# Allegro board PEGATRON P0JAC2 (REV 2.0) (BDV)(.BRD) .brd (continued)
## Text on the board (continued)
BOTTOM: list("[Spacing] BOTTOM" "17.Line to Route Keepout" "0 MIL [DEFAULT]" "0 MIL" "0.00 MIL" "DRC ERROR CLASS/BOTTOM" "[Shape] Route Keepout/All ((-570.0 2225.0) (410.0 2765.0))" "[Line] +V3P3S_VIB ((-596.0 2584.2) (-558.0 2622.2))" list(-575.530000 2604.670000) nil)@@@list("bobo_dong" "2014/01/13 20:58:57" nil "S0DCOA89102" "g1t-p0jac.11")@@@nil | list("[Spacing] BOTTOM" "18.Line to Route Keepout" "0 MIL [DEFAULT]" "0 MIL" "0.00 MIL" "DRC ERROR CLASS/BOTTOM" "[Shape] Route Keepout/All ((-570.0 2225.0) (410.0 2765.0))" "[Line] +V3P3S_VIB ((-574.0 2606.2) (-529.72 2618.2))" list(-556.940000 2612.200000) nil)@@@list("bobo_dong" "2014/01/13 20:58:59" nil "S0DCOA89102" "g1t-p0jac.11")@@@nil | list("[Spacing] BOTTOM" "16.Microvia to Route Keepout" "0 MIL [DEFAULT]" "0 MIL" "0.00 MIL" "DRC ERROR CLASS/BOTTOM" "[Shape] Route Keepout/All ((-570.0 2225.0) (410.0 2765.0))" "[B/BVia] AU_HP_L (VIA10D4A24-L7-BOT) (-535.72 2513.77)" list(-532.440000 2510.000000) nil)@@@list("bobo_dong" "2014/01/13 20:58:57" nil "S0DCOA89102" "g1t-p0jac.11")@@@nil | list("[Spacing] BOTTOM" "8.Microvia to Route Keepout" "0 MIL [DEFAULT]" "OVERLAP" "" "DRC ERROR CLASS/BOTTOM" "[Shape] Route Keepout/All ((-570.0 2225.0) (410.0 2765.0))" "[B/BVia] AGND_AUD (VIA10D4A24-L7-BOT) (-535.72 2592.51)" list(-531.380000 2595.000000) nil)@@@list("bobo_dong" "2014/01/13 20:58:46" nil "S0DCOA89102" "g1t-p0jac.11")@@@nil | list("[Spacing] BOTTOM" "1.Line to Route Keepout" "0 MIL [DEFAULT]" "0 MIL" "0.00 MIL" "DRC ERROR CLASS/BOTTOM" "[Shape] Route Keepout/Bottom ((-570.0 2225.0) (175.0 2751.43))" "[Line] AGND_AUD ((-541.72 2606.2) (-489.2 2618.2))" list(-530.500000 2612.200000) nil)@@@list("bobo_dong" "2014/02/26 15:13:36" nil "S0DCOA89102" "g1t-p0jac.11")@@@list("vincent_kuo" "2014/02/26 15:23:34" nil "VINCENT_KUO-PC" "g1t-p0jac_byt-t.14") | list("[Spacing] BOTTOM" "2.Line to Route Keepout" "0 MIL [DEFAULT]" "0 MIL" "0.00 MIL" "DRC ERROR CLASS/BOTTOM" "[Shape] Route Keepout/Bottom ((-570.0 2225.0) (200.0 2751.43))" "[Line] AGND_AUD ((-541.72 2606.2) (-489.2 2618.2))" list(-530.500000 2612.200000) nil)@@@list("bobo_dong" "2014/02/27 14:44:05" nil "S0DCOA89102" "g1t-p0jac.11")@@@list("vincent_kuo" "2014/02/27 14:51:22" nil "VINCENT_KUO-PC" "g1t-p0jac_byt-t.14") | list("[Spacing] BOTTOM" "27.Line to Route Keepout" "0 MIL [DEFAULT]" "0 MIL" "0.00 MIL" "DRC ERROR CLASS/BOTTOM" "[Shape] Route Keepout/All ((-570.0 2225.0) (410.0 2765.0))" "[Line] GND ((-541.72 2488.09) (-513.09 2500.09))" list(-527.400000 2494.090000) nil)@@@list("bobo_dong" "2014/01/13 20:59:13" nil "S0DCOA89102" "g1t-p0jac.11")@@@nil | list("[Spacing] BOTTOM" "28.Line to Route Keepout" "0 MIL [DEFAULT]" "0 MIL" "0.00 MIL" "DRC ERROR CLASS/BOTTOM" "[Shape] Route Keepout/All ((-570.0 2225.0) (410.0 2765.0))" "[Line] GND ((-525.09 2473.0) (-498.0 2500.09))" list(-515.000000 2490.000000) nil)@@@list("bobo_dong" "2014/01/13 20:59:14" nil "S0DCOA89102" "g1t-p0jac.11")@@@nil | list("[Spacing] BOTTOM" "2.Line to Route Keepout" "0 MIL [DEFAULT]" "0 MIL" "0.00 MIL" "DRC ERROR CLASS/BOTTOM" "[Shape] Route Keepout/Bottom ((-570.0 2225.0) (175.0 2751.43))" "[Line] AGND_AUD ((-501.2 2586.0) (-469.0 2618.2))" list(-482.560000 2599.560000) nil)@@@list("bobo_dong" "2014/02/26 15:13:34" nil "S0DCOA89102" "g1t-p0jac.11")@@@list("vincent_kuo" "2014/02/26 15:23:34" nil "VINCENT_KUO-PC" "g1t-p0jac_byt-t.14") | list("[Spacing] BOTTOM" "3.Line to Route Keepout" "0 MIL [DEFAULT]" "0 MIL" "0.00 MIL" "DRC ERROR CLASS/BOTTOM" "[Shape] Route Keepout/Bottom ((-570.0 2225.0) (200.0 2751.43))" "[Line] AGND_AUD ((-501.2 2586.0) (-469.0 2618.2))" list(-482.560000 2599.560000) nil)@@@list("bobo_dong" "2014/02/27 14:44:01" nil "S0DCOA89102" "g1t-p0jac.11")@@@list("vincent_kuo" "2014/02/27 14:51:23" nil "VINCENT_KUO-PC" "g1t-p0jac_byt-t.14") | list("[Spacing] BOTTOM" "82.Shape to Route Keepout" "0 MIL [DEFAULT]" "0 MIL" "0.00 MIL" "DRC ERROR CLASS/BOTTOM" "[Shape] Route Keepout/Bottom ((-271.91 4409.28) (9.9 4687.15))" "[Bottom Shape] GND ((-679.11 -19.37) (3281.09 4854.01))" list(-261.910000 4409.280000) nil)@@@list("bobo_dong" "2014/01/13 20:49:14" nil "S0DCOA89102" "g1t-p0jac.11")@@@nil | list("[Spacing] BOTTOM" "1.Shape to Route Keepin" "0 MIL [DEFAULT]" "0 MIL" "0.00 MIL" "DRC ERROR CLASS/BOTTOM" "[Shape] Route Keepin/All ((-679.11 -19.37) (3281.09 4854.01))" "[Bottom Shape] GND ((-679.11 -19.37) (3281.09 4854.01))" list(-241.750000 4716.530000) nil)@@@list("vincent_kuo" "2014/01/15 11:51:28" nil "VINCENT_KUO-PC" "g1t-p0jac_byt-t.12")@@@list("jennifer_hsu" "2014/01/15 11:31:33" nil "JENNIFER_H-PC" "g1t-p0jac_byt-t.12") | list("[Spacing] BOTTOM" "73.Shape to Route Keepin" "0 MIL [DEFAULT]" "0 MIL" "0.00 MIL" "DRC ERROR CLASS/BOTTOM" "[Shape] Route Keepin/All ((-679.11 -19.37) (3281.09 4854.01))" "[Bottom Shape] GND ((-261.91 4419.28) (-0.1 4677.15))" list(-226.620000 4676.940000) nil)@@@list("bobo_dong" "2014/01/13 20:48:37" nil "S0DCOA89102" "g1t-p0jac.11")@@@nil | list("[Spacing] BOTTOM" "8.Shape to Route Keepin" "0 MIL [DEFAULT]" "0 MIL" "0.00 MIL" "DRC ERROR CLASS/BOTTOM" "[Shape] Route Keepin/All ((-679.03 -19.38) (3281.17 4854.0))" "[Bottom Shape] GND ((-679.11 -19.37) (3281.09 4854.01))" list(-19.380000 -0.010000) nil)@@@list("bobo_dong" "2014/02/26 15:13:26" nil "S0DCOA89102" "g1t-p0jac.11")@@@list("vincent_kuo" "2014/02/26 12:03:50" nil "VINCENT_KUO-PC" "g1t-p0jac_byt-t.14") | list("[Spacing] BOTTOM" "78.Shape to Route Keepout" "0 MIL [DEFAULT]" "0 MIL" "0.00 MIL" "DRC ERROR CLASS/BOTTOM" "[Shape] Route Keepout/All ((-570.0 2225.0) (410.0 2765.0))" "[Bottom Shape] GND ((-679.11 -19.37) (3281.09 4854.01))" list(64.990000 2610.850000) nil)@@@list("bobo_dong" "2014/01/13 20:49:11" nil "S0DCOA89102" "g1t-p0jac.11")@@@nil | list("[Spacing] BOTTOM" "1.Shape to Route Keepout" "0 MIL [DEFAULT]" "0 MIL" "0.00 MIL" "DRC ERROR CLASS/BOTTOM" "[Shape] Route Keepout/Bottom ((-570.0 2225.0) (200.0 2751.43))" "[Bottom Shape] GND ((-679.11 -19.37) (3281.09 4854.01))" list(65.000000 2610.860000) nil)@@@list("bobo_dong" "2014/02/27 14:43:52" nil "S0DCOA89102" "g1t-p0jac.11")@@@list("vincent_kuo" "2014/02/27 14:51:21" nil "VINCENT_KUO-PC" "g1t-p0jac_byt-t.14") | list("[Spacing] BOTTOM" "12.Shape to Route Keepout" "0 MIL [DEFAULT]" "0 MIL" "0.00 MIL" "DRC ERROR CLASS/BOTTOM" "[Shape] Route Keepout/Bottom ((-570.0 2225.0) (175.0 2751.43))" "[Bottom Shape] GND ((-679.11 -19.37) (3281.09 4854.01))" list(65.000000 2610.860000) nil)@@@list("bobo_dong" "2014/02/25 09:09:09" nil "s0dcoa89102" "g1t-p0jac.11")@@@list("vincent_kuo" "2014/02/26 12:03:59" nil "VINCENT_KUO-PC" "g1t-p0jac_byt-t.14") | list("[Spacing] BOTTOM" "31.Line to Route Keepout" "0 MIL [DEFAULT]" "0 MIL" "0.00 MIL" "DRC ERROR CLASS/BOTTOM" "[Shape] Route Keepout/All ((-570.0 2225.0) (410.0 2765.0))" "[Line] +V1P8S ((86.6 2695.11) (96.6 2791.23))" list(91.600000 2725.460000) nil)@@@list("bobo_dong" "2014/01/13 20:59:18" nil "S0DCOA89102" "g1t-p0jac.11")@@@nil | list("[Spacing] BOTTOM" "30.Line to Route Keepout" "0 MIL [DEFAULT]" "0 MIL" "0.00 MIL" "DRC ERROR CLASS/BOTTOM" "[Shape] Route Keepout/All ((-570.0 2225.0) (410.0 2765.0))" "[Line] GND ((117.23 2762.48) (134.23 2801.98))" list(125.730000 2770.980000) nil)@@@list("bobo_dong" "2014/01/13 20:59:16" nil "S0DCOA89102" "g1t-p0jac.11")@@@nil | list("[Physical] BOTTOM" "10.Pad/Pad Direct Connect" "VIAS_PINS_ONLY [85OHM(DP_#1/#2/5/200)]" "ALL_ALLOWED" "" "DRC ERROR CLASS/BOTTOM" "[SmdPin] MCSI_2_CLK_DP_CON (<uTiL>cId875<uTiL>.3) (130.9 3857.59)" "[SmdPin] MCSI_2_CLK_DP_CON (<uTiL>cId2109<uTiL>.4) (128.93 3855.62)" list(128.930000 3855.620000) nil)@@@list("bobo_dong" "2014/01/27 15:52:09" nil "s0dcoa89102" "g1t-p0jac.11")@@@list("vincent_kuo" "2014/02/26 15:23:44" nil "VINCENT_KUO-PC" "g1t-p0jac_byt-t.14") | list("[Physical] BOTTOM" "11.Pad/Pad Direct Connect" "VIAS_PINS_ONLY [85OHM(DP_#1/#2/5/200)]" "ALL_ALLOWED" "" "DRC ERROR CLASS/BOTTOM" "[SmdPin] MCSI_2_CLK_DP (<uTiL>cId875<uTiL>.4) (130.9 3808.37)" "[SmdPin] MCSI_2_CLK_DP (<uTiL>cId2109<uTiL>.3) (128.93 3810.34)" list(128.930000 3810.340000) nil)@@@list("bobo_dong" "2014/01/27 15:52:10" nil "s0dcoa89102" "g1t-p0jac.11")@@@list("vincent_kuo" "2014/02/26 15:23:46" nil "VINCENT_KUO-PC" "g1t-p0jac_byt-t.14") | list("[Physical] BOTTOM" "9.Pad/Pad Direct Connect" "VIAS_PINS_ONLY [85OHM(DP_#1/#2/5/200)]" "ALL_ALLOWED" "" "DRC ERROR CLASS/BOTTOM" "[SmdPin] MCSI_2_CLK_DN_CON (<uTiL>cId875<uTiL>.2) (152.56 3857.59)" "[SmdPin] MCSI_2_CLK_DN_CON (<uTiL>cId2109<uTiL>.2) (154.53 3855.62)" list(154.530000 3855.620000) nil)@@@list("bobo_dong" "2014/01/27 15:52:08" nil "s0dcoa89102" "g1t-p0jac.11")@@@list("vincent_kuo" "2014/02/26 15:23:43" nil "VINCENT_KUO-PC" "g1t-p0jac_byt-t.14") | list("[Physical] BOTTOM" "8.Pad/Pad Direct Connect" "VIAS_PINS_ONLY [85OHM(DP_#1/#2/5/200)]" "ALL_ALLOWED" "" "DRC ERROR CLASS/BOTTOM" "[SmdPin] MCSI_2_CLK_DN (<uTiL>cId875<uTiL>.1) (152.56 3808.37)" "[SmdPin] MCSI_2_CLK_DN (<uTiL>cId2109<uTiL>.1) (154.53 3810.34)" list(154.530000 3810.340000) nil)@@@list("bobo_dong" "2014/01/27 15:52:07" nil "s0dcoa89102" "g1t-p0jac.11")@@@list("vincent_kuo" "2014/02/26 15:23:42" nil "VINCENT_KUO-PC" "g1t-p0jac_byt-t.14") | list("[Spacing] BOTTOM" "29.Line to Route Keepout" "0 MIL [DEFAULT]" "0 MIL" "0.00 MIL" "DRC ERROR CLASS/BOTTOM" "[Shape] Route Keepout/All ((-570.0 2225.0) (410.0 2765.0))" "[Line] GND ((148.23 2762.48) (165.23 2795.77))" list(156.730000 2770.980000) nil)@@@list("bobo_dong" "2014/01/13 20:59:16" nil "S0DCOA89102" "g1t-p0jac.11")@@@nil | list("[Physical] BOTTOM" "5.Pad/Pad Direct Connect" "VIAS_PINS_ONLY [85OHM(DP_#1/#2/5/200)]" "ALL_ALLOWED" "" "DRC ERROR CLASS/BOTTOM" "[SmdPin] MCSI_2_DATA_DP_CON (<uTiL>cId876<uTiL>.3) (178.9 3857.59)" "[SmdPin] MCSI_2_DATA_DP_CON (<uTiL>cId2108<uTiL>.4) (176.93 3855.62)" list(176.930000 3855.620000) nil)@@@list("bobo_dong" "2014/01/27 15:52:04" nil "s0dcoa89102" "g1t-p0jac.11")@@@list("vincent_kuo" "2014/02/26 15:23:39" nil "VINCENT_KUO-PC" "g1t-p0jac_byt-t.14") | list("[Physical] BOTTOM" "4.Pad/Pad Direct Connect" "VIAS_PINS_ONLY [85OHM(DP_#1/#2/5/200)]" "ALL_ALLOWED" "" "DRC ERROR CLASS/BOTTOM" "[SmdPin] MCSI_2_DATA_DP (<uTiL>cId876<uTiL>.4) (178.9 3808.37)" "[SmdPin] MCSI_2_DATA_DP (<uTiL>cId2108<uTiL>.3) (176.93 3810.34)" list(176.930000 3810.340000) nil)@@@list("bobo_dong" "2014/01/27 15:52:03" nil "s0dcoa89102" "g1t-p0jac.11")@@@list("vincent_kuo" "2014/02/26 15:23:38" nil "VINCENT_KUO-PC" "g1t-p0jac_byt-t.14") | list("[Spacing] BOTTOM" "80.Shape to Route Keepout" "0 MIL [DEFAULT]" "0 MIL" "0.00 MIL" "DRC ERROR CLASS/BOTTOM" "[Shape] Route Keepout/All ((175.42 4013.55) (297.04 4057.17))" "[Bottom Shape] GND ((-679.11 -19.37) (3281.09 4854.01))" list(197.230000 4057.170000) nil)@@@list("bobo_dong" "2014/01/13 20:49:12" nil "S0DCOA89102" "g1t-p0jac.11")@@@nil | list("[Physical] BOTTOM" "6.Pad/Pad Direct Connect" "VIAS_PINS_ONLY [85OHM(DP_#1/#2/5/200)]" "ALL_ALLOWED" "" "DRC ERROR CLASS/BOTTOM" "[SmdPin] MCSI_2_DATA_DN_CON (<uTiL>cId876<uTiL>.2) (200.56 3857.59)" "[SmdPin] MCSI_2_DATA_DN_CON (<uTiL>cId2108<uTiL>.2) (202.53 3855.62)" list(202.530000 3855.620000) nil)@@@list("bobo_dong" "2014/01/27 15:52:05" nil "s0dcoa89102" "g1t-p0jac.11")@@@list("vincent_kuo" "2014/02/26 15:23:40" nil "VINCENT_KUO-PC" "g1t-p0jac_byt-t.14") | list("[Physical] BOTTOM" "7.Pad/Pad Direct Connect" "VIAS_PINS_ONLY [85OHM(DP_#1/#2/5/200)]" "ALL_ALLOWED" "" "DRC ERROR CLASS/BOTTOM" "[SmdPin] MCSI_2_DATA_DN (<uTiL>cId876<uTiL>.1) (200.56 3808.37)" "[SmdPin] MCSI_2_DATA_DN (<uTiL>cId2108<uTiL>.1) (202.53 3810.34)" list(202.530000 3810.340000) nil)@@@list("bobo_dong" "2014/01/27 15:52:06" nil "s0dcoa89102" "g1t-p0jac.11")@@@list("vincent_kuo" "2014/02/26 15:23:41" nil "VINCENT_KUO-PC" "g1t-p0jac_byt-t.14") | list("[Spacing] BOTTOM" "81.Shape to Route Keepin" "0 MIL [DEFAULT]" "0 MIL" "0.00 MIL" "DRC ERROR CLASS/BOTTOM" "[Shape] Route Keepin/All ((-679.11 -19.37) (3281.09 4854.01))" "[Bottom Shape] GND ((-679.11 -19.37) (3281.09 4854.01))" list(204.240000 4334.330000) nil)@@@list("bobo_dong" "2014/01/13 20:49:13" nil "S0DCOA89102" "g1t-p0jac.11")@@@nil | list("[Spacing] BOTTOM" "26.Line to Route Keepout" "0 MIL [DEFAULT]" "0 MIL" "0.00 MIL" "DRC ERROR CLASS/BOTTOM" "[Shape] Route Keepout/All ((-570.0 2225.0) (410.0 2765.0))" "[Line] CPVPP ((257.91 2632.09) (277.03 2639.09))" list(273.530000 2635.590000) nil)@@@list("bobo_dong" "2014/01/13 20:59:12" nil "S0DCOA89102" "g1t-p0jac.11")@@@nil | list("[Spacing] BOTTOM" "7.Line to Route Keepout" "0 MIL [DEFAULT]" "0 MIL" "0.00 MIL" "DRC ERROR CLASS/BOTTOM" "[Shape] Route Keepout/All ((-570.0 2225.0) (410.0 2765.0))" "[Line] +V1P8S_AUD_PVDD ((253.35 2616.35) (277.03 2623.35))" list(273.530000 2619.850000) nil)@@@list("bobo_dong" "2014/01/13 20:58:45" nil "S0DCOA89102" "g1t-p0jac.11")@@@nil | list("[Spacing] BOTTOM" "24.Line to Route Keepout" "0 MIL [DEFAULT]" "0 MIL" "0.00 MIL" "DRC ERROR CLASS/BOTTOM" "[Shape] Route Keepout/All ((-570.0 2225.0) (410.0 2765.0))" "[Line] N55583183 ((249.15 2584.85) (277.03 2591.85))" list(273.530000 2588.350000) nil)@@@list("bobo_dong" "2014/01/13 20:59:07" nil "S0DCOA89102" "g1t-p0jac.11")@@@nil | list("[Spacing] BOTTOM" "19.Line to Route Keepout" "0 MIL [DEFAULT]" "0 MIL" "0.00 MIL" "DRC ERROR CLASS/BOTTOM" "[Shape] Route Keepout/All ((-570.0 2225.0) (410.0 2765.0))" "[Line] N55583175 ((250.9 2569.1) (277.03 2576.1))" list(273.530000 2572.600000) nil)@@@list("bobo_dong" "2014/01/13 20:59:00" nil "S0DCOA89102" "g1t-p0jac.11")@@@nil | list("[Spacing] BOTTOM" "20.Line to Route Keepout" "0 MIL [DEFAULT]" "0 MIL" "0.00 MIL" "DRC ERROR CLASS/BOTTOM" "[Shape] Route Keepout/All ((-570.0 2225.0) (410.0 2765.0))" "[Line] N55583031 ((251.61 2537.61) (277.03 2544.61))" list(273.530000 2541.110000) nil)@@@list("bobo_dong" "2014/01/13 20:59:00" nil "S0DCOA89102" "g1t-p0jac.11")@@@nil | list("[Spacing] BOTTOM" "11.Line to Route Keepout" "0 MIL [DEFAULT]" "0 MIL" "0.00 MIL" "DRC ERROR CLASS/BOTTOM" "[Shape] Route Keepout/All ((-570.0 2225.0) (410.0 2765.0))" "[Line] N55584679 ((251.64 2490.36) (277.03 2497.36))" list(273.530000 2493.860000) nil)@@@list("bobo_dong" "2014/01/13 20:58:50" nil "S0DCOA89102" "g1t-p0jac.11")@@@nil | list("[Spacing] BOTTOM" "9.Microvia to Route Keepout" "0 MIL [DEFAULT]" "OVERLAP" "" "DRC ERROR CLASS/BOTTOM" "[Shape] Route Keepout/All ((-570.0 2225.0) (410.0 2765.0))" "[B/BVia] AGND_AUD (VIA10D4A24-L7-BOT) (273.53 2604.1)" list(275.000000 2608.880000) nil)@@@list("bobo_dong" "2014/01/13 20:58:47" nil "S0DCOA89102" "g1t-p0jac.11")@@@nil | list("[Spacing] BOTTOM" "25.Microvia to Route Keepout" "0 MIL [DEFAULT]" "0 MIL" "0.00 MIL" "DRC ERROR CLASS/BOTTOM" "[Shape] Route Keepout/All ((-570.0 2225.0) (410.0 2765.0))" "[B/BVia] N55582751 (VIA10D4A24-L7-BOT) (273.53 2556.85)" list(275.000000 2561.630000) nil)@@@list("bobo_dong" "2014/01/13 20:59:08" nil "S0DCOA89102" "g1t-p0jac.11")@@@nil | list("[Spacing] BOTTOM" "23.Line to Route Keepout" "0 MIL [DEFAULT]" "0 MIL" "0.00 MIL" "DRC ERROR CLASS/BOTTOM" "[Shape] Route Keepout/All ((-570.0 2225.0) (410.0 2765.0))" "[Line] N60826251 ((231.59 2431.0) (303.34 2441.0))" list(294.600000 2436.000000) nil)@@@list("bobo_dong" "2014/01/13 20:59:06" nil "S0DCOA89102" "g1t-p0jac.11")@@@nil | list("[Spacing] BOTTOM" "22.Line to Route Keepout" "0 MIL [DEFAULT]" "0 MIL" "0.00 MIL" "DRC ERROR CLASS/BOTTOM" "[Shape] Route Keepout/All ((-570.0 2225.0) (410.0 2765.0))" "[Line] N60826251 ((294.84 2432.5) (302.62 2440.28))" list(299.120000 2436.780000) nil)@@@list("bobo_dong" "2014/01/13 20:59:04" nil "S0DCOA89102" "g1t-p0jac.11")@@@nil | list("[Physical] BOTTOM" "101.Pad/Pad Direct Connect" "VIAS_PINS_ONLY [(GND_DEFAULT)]" "ALL_ALLOWED" "" "DRC ERROR CLASS/BOTTOM" "[ThruPin] GND (<uTiL>cId50<uTiL>.52) (306.23 2628.48)" "[SmdPin] GND (<uTiL>cId50<uTiL>.49) (385.73 2548.98)" list(306.230000 2628.480000) nil)@@@list("bobo_dong" "2014/01/27 15:53:54" nil "s0dcoa89102" "g1t-p0jac.11")@@@list("vincent_kuo" "2014/02/26 15:25:41" nil "VINCENT_KUO-PC" "g1t-p0jac_byt-t.14") | list("[Physical] BOTTOM" "100.Pad/Pad Direct Connect" "VIAS_PINS_ONLY [(GND_DEFAULT)]" "ALL_ALLOWED" "" "DRC ERROR CLASS/BOTTOM" "[ThruPin] GND (<uTiL>cId50<uTiL>.56) (306.23 2548.98)" "[SmdPin] GND (<uTiL>cId50<uTiL>.49) (385.73 2548.98)" list(306.230000 2548.980000) nil)@@@list("bobo_dong" "2014/01/27 15:53:53" nil "s0dcoa89102" "g1t-p0jac.11")@@@list("vincent_kuo" "2014/02/26 15:25:40" nil "VINCENT_KUO-PC" "g1t-p0jac_byt-t.14") | list("[Physical] BOTTOM" "104.Pad/Pad Direct Connect" "VIAS_PINS_ONLY [(GND_DEFAULT)]" "ALL_ALLOWED" "" "DRC ERROR CLASS/BOTTOM" "[ThruPin] GND (<uTiL>cId50<uTiL>.59) (306.23 2469.48)" "[SmdPin] GND (<uTiL>cId50<uTiL>.49) (385.73 2548.98)" list(306.230000 2469.480000) nil)@@@list("bobo_dong" "2014/01/27 15:53:57" nil "s0dcoa89102" "g1t-p0jac.11")@@@list("vincent_kuo" "2014/02/26 15:25:44" nil "VINCENT_KUO-PC" "g1t-p0jac_byt-t.14") | list("[Spacing] BOTTOM" "12.Line to Route Keepout" "0 MIL [DEFAULT]" "0 MIL" "0.00 MIL" "DRC ERROR CLASS/BOTTOM" "[Shape] Route Keepout/All ((-570.0 2225.0) (410.0 2765.0))" "[Line] N60826256 ((311.36 2420.96) (318.36 2440.28))" list(314.860000 2436.780000) nil)@@@list("bobo_dong" "2014/01/13 20:58:51" nil "S0DCOA89102" "g1t-p0jac.11")@@@nil | list("[Spacing] BOTTOM" "6.Line to Route Keepout" "0 MIL [DEFAULT]" "0 MIL" "0.00 MIL" "DRC ERROR CLASS/BOTTOM" "[Shape] Route Keepout/All ((-570.0 2225.0) (410.0 2765.0))" "[Line] N60556074 ((327.11 2419.02) (334.11 2440.28))" list(330.610000 2436.780000) nil)@@@list("bobo_dong" "2014/01/13 20:58:44" nil "S0DCOA89102" "g1t-p0jac.11")@@@nil | list("[Spacing] BOTTOM" "13.Line to Route Keepout" "0 MIL [DEFAULT]" "0 MIL" "0.00 MIL" "DRC ERROR CLASS/BOTTOM" "[Shape] Route Keepout/All ((-570.0 2225.0) (410.0 2765.0))" "[Line] AU_HP_L ((337.3 2708.54) (349.86 2721.1))" list(346.360000 2712.040000) nil)@@@list("bobo_dong" "2014/01/13 20:58:54" nil "S0DCOA89102" "g1t-p0jac.11")@@@nil | list("[Spacing] BOTTOM" "14.Line to Route Keepout" "0 MIL [DEFAULT]" "0 MIL" "0.00 MIL" "DRC ERROR CLASS/BOTTOM" "[Shape] Route Keepout/All ((-570.0 2225.0) (410.0 2765.0))" "[Line] AU_HP_L ((342.86 2657.68) (349.86 2715.54))" list(346.360000 2661.640000) nil)@@@list("bobo_dong" "2014/01/13 20:58:54" nil "S0DCOA89102" "g1t-p0jac.11")@@@nil | list("[Spacing] BOTTOM" "97.Line to Route Keepout" "0 MIL [DEFAULT]" "0 MIL" "0.00 MIL" "DRC ERROR CLASS/BOTTOM" "[Shape] Route Keepout/All ((-570.0 2225.0) (410.0 2765.0))" "[Line] AGND_AUD ((342.86 2412.14) (349.86 2440.28))" list(346.360000 2436.780000) nil)@@@list("bobo_dong" "2014/01/13 20:51:46" nil "S0DCOA89102" "g1t-p0jac.11")@@@nil | list("[Spacing] BOTTOM" "15.Thru Via to Route Keepout" "0 MIL [DEFAULT]" "0 MIL" "0.00 MIL" "DRC ERROR CLASS/BOTTOM" "[Shape] Route Keepout/All ((-570.0 2225.0) (410.0 2765.0))" "[ThruVia] AU_HP_L (VIA20D10A32) (340.8 2717.6)" list(350.000000 2721.520000) nil)@@@list("bobo_dong" "2014/01/13 20:58:55" nil "S0DCOA89102" "g1t-p0jac.11")@@@nil | list("[Spacing] BOTTOM" "74.Shape to Route Keepout" "0 MIL [DEFAULT]" "0 MIL" "0.00 MIL" "DRC ERROR CLASS/BOTTOM" "[Shape] Route Keepout/All ((-570.0 2225.0) (410.0 2765.0))" "[Bottom Shape] GND ((294.0 2458.0) (477.0 2640.0))" list(351.640000 2640.000000) nil)@@@list("bobo_dong" "2014/01/13 20:49:07" nil "S0DCOA89102" "g1t-p0jac.11")@@@nil | list("[Physical] BOTTOM" "98.Pad/Pad Direct Connect" "VIAS_PINS_ONLY [(GND_DEFAULT)]" "ALL_ALLOWED" "" "DRC ERROR CLASS/BOTTOM" "[ThruPin] GND (<uTiL>cId50<uTiL>.55) (359.23 2548.98)" "[SmdPin] GND (<uTiL>cId50<uTiL>.49) (385.73 2548.98)" list(359.230000 2548.980000) nil)@@@list("bobo_dong" "2014/01/27 15:53:51" nil "s0dcoa89102" "g1t-p0jac.11")@@@list("vincent_kuo" "2014/02/26 15:25:38" nil "VINCENT_KUO-PC" "g1t-p0jac_byt-t.14") | list("[Spacing] BOTTOM" "10.Line to Route Keepout" "0 MIL [DEFAULT]" "0 MIL" "0.00 MIL" "DRC ERROR CLASS/BOTTOM" "[Shape] Route Keepout/All ((-570.0 2225.0) (410.0 2765.0))" "[Line] LRCK2 ((358.61 2657.68) (365.61 2721.61))" list(362.110000 2699.530000) nil)@@@list("bobo_dong" "2014/01/13 20:58:49" nil "S0DCOA89102" "g1t-p0jac.11")@@@nil | list("[Spacing] BOTTOM" "5.Line to Route Keepout" "0 MIL [DEFAULT]" "0 MIL" "0.00 MIL" "DRC ERROR CLASS/BOTTOM" "[Shape] Route Keepout/All ((-570.0 2225.0) (410.0 2765.0))" "[Line] IN2N ((357.11 2406.31) (367.11 2441.78))" list(362.110000 2436.780000) nil)@@@list("bobo_dong" "2014/01/13 20:58:43" nil "S0DCOA89102" "g1t-p0jac.11")@@@nil | list("[Spacing] BOTTOM" "21.Line to Route Keepout" "0 MIL [DEFAULT]" "0 MIL" "0.00 MIL" "DRC ERROR CLASS/BOTTOM" "[Shape] Route Keepout/All ((-570.0 2225.0) (410.0 2765.0))" "[Line] IN2P ((372.86 2382.86) (382.86 2441.78))" list(377.860000 2436.780000) nil)@@@list("bobo_dong" "2014/01/13 20:59:01" nil "S0DCOA89102" "g1t-p0jac.11")@@@nil | list("[Physical] BOTTOM" "99.Pad/Pad Direct Connect" "VIAS_PINS_ONLY [(GND_DEFAULT)]" "ALL_ALLOWED" "" "DRC ERROR CLASS/BOTTOM" "[ThruPin] GND (<uTiL>cId50<uTiL>.51) (385.73 2628.48)" "[SmdPin] GND (<uTiL>cId50<uTiL>.49) (385.73 2548.98)" list(385.730000 2628.480000) nil)@@@list("bobo_dong" "2014/01/27 15:53:52" nil "s0dcoa89102" "g1t-p0jac.11")@@@list("vincent_kuo" "2014/02/26 15:25:39" nil "VINCENT_KUO-PC" "g1t-p0jac_byt-t.14") | list("[Physical] BOTTOM" "103.Pad/Pad Direct Connect" "VIAS_PINS_ONLY [(GND_DEFAULT)]" "ALL_ALLOWED" "" "DRC ERROR CLASS/BOTTOM" "[ThruPin] GND (<uTiL>cId50<uTiL>.58) (385.73 2469.48)" "[SmdPin] GND (<uTiL>cId50<uTiL>.49) (385.73 2548.98)" list(385.730000 2469.480000) nil)@@@list("bobo_dong" "2014/01/27 15:53:56" nil "s0dcoa89102" "g1t-p0jac.11")@@@list("vincent_kuo" "2014/02/26 15:25:43" nil "VINCENT_KUO-PC" "g1t-p0jac_byt-t.14") | list("[Spacing] BOTTOM" "75.Shape to Route Keepout" "0 MIL [DEFAULT]" "0 MIL" "0.00 MIL" "DRC ERROR CLASS/BOTTOM" "[Shape] Route Keepout/All ((346.29 437.2) (389.92 558.82))" "[Bottom Shape] GND ((-679.11 -19.37) (3281.09 4854.01))" list(389.920000 537.010000) nil)@@@list("bobo_dong" "2014/01/13 20:49:09" nil "S0DCOA89102" "g1t-p0jac.11")@@@nil | list("[Spacing] BOTTOM" "94.Microvia to Route Keepout" "0 MIL [DEFAULT]" "0 MIL" "0.00 MIL" "DRC ERROR CLASS/BOTTOM" "[Shape] Route Keepout/All ((-570.0 2225.0) (410.0 2765.0))" "[B/BVia] DMIC1_DAT (VIA10D4A24-L7-BOT) (409.35 2436.78)" list(410.000000 2441.740000) nil)@@@list("bobo_dong" "2014/01/13 20:51:38" nil "S0DCOA89102" "g1t-p0jac.11")@@@nil | list("[Physical] BOTTOM" "97.Pad/Pad Direct Connect" "VIAS_PINS_ONLY [(GND_DEFAULT)]" "ALL_ALLOWED" "" "DRC ERROR CLASS/BOTTOM" "[ThruPin] GND (<uTiL>cId50<uTiL>.54) (412.23 2548.98)" "[SmdPin] GND (<uTiL>cId50<uTiL>.49) (385.73 2548.98)" list(412.230000 2548.980000) nil)@@@list("bobo_dong" "2014/01/27 15:53:50" nil "s0dcoa89102" "g1t-p0jac.11")@@@list("vincent_kuo" "2014/02/26 15:25:36" nil "VINCENT_KUO-PC" "g1t-p0jac_byt-t.14") | list("[Spacing] BOTTOM" "95.Microvia to Route Keepout" "0 MIL [DEFAULT]" "0 MIL" "0.00 MIL" "DRC ERROR CLASS/BOTTOM" "[Shape] Route Keepout/All ((155.0 2225.0) (480.0 2457.5))" "[B/BVia] DMIC1_DAT (VIA10D4A24-L7-BOT) (409.35 2436.78)" list(414.300000 2437.500000) nil)@@@list("bobo_dong" "2014/01/13 20:51:39" nil "S0DCOA89102" "g1t-p0jac.11")@@@nil | list("[Spacing] BOTTOM" "88.Microvia to Route Keepout" "0 MIL [DEFAULT]" "0 MIL" "0.00 MIL" "DRC ERROR CLASS/BOTTOM" "[Shape] Route Keepout/All ((155.0 2225.0) (480.0 2457.5))" "[B/BVia] MICBIAS1 (VIA10D4A24-L7-BOT) (425.1 2436.78)" list(420.950000 2434.000000) nil)@@@list("bobo_dong" "2014/01/13 20:50:40" nil "S0DCOA89102" "g1t-p0jac.11")@@@nil | list("[Spacing] BOTTOM" "5.Line to Route Keepout" "0 MIL [DEFAULT]" "0 MIL" "0.00 MIL" "DRC ERROR CLASS/BOTTOM" "[Shape] Route Keepout/All ((155.0 2225.0) (480.0 2457.5))" "[Line] +V3P3S_AUD ((420.73 2347.98) (430.73 2404.03))" list(425.730000 2390.130000) nil)@@@list("bobo_dong" "2014/01/13 21:08:41" nil "S0DCOA89102" "g1t-p0jac.11")@@@nil | list("[Physical] BOTTOM" "53.Pad/Pad Direct Connect" "VIAS_PINS_ONLY [DEFAULT]" "ALL_ALLOWED" "" "DRC ERROR CLASS/BOTTOM" "[SmdPin] N60977672 (<uTiL>cId4105<uTiL>.1) (450.98 1817.84)" "[SmdPin] N60977672 (<uTiL>cId3335<uTiL>.2) (430.98 1830.27)" list(430.980000 1830.270000) nil)@@@list("bobo_dong" "2014/01/27 15:53:00" nil "s0dcoa89102" "g1t-p0jac.11")@@@list("vincent_kuo" "2014/02/26 15:24:38" nil "VINCENT_KUO-PC" "g1t-p0jac_byt-t.14") | list("[Spacing] BOTTOM" "114.Line to Route Keepout" "0 MIL [DEFAULT]" "0 MIL" "0.00 MIL" "DRC ERROR CLASS/BOTTOM" "[Shape] Route Keepout/All ((155.0 2225.0) (480.0 2457.5))" "[Line] +V3P3S_AUD ((420.73 2362.73) (445.85 2387.85))" list(436.930000 2378.930000) nil)@@@list("bobo_dong" "2014/01/13 20:52:17" nil "S0DCOA89102" "g1t-p0jac.11")@@@nil | list("[Spacing] BOTTOM" "4.Line to Route Keepout" "0 MIL [DEFAULT]" "0 MIL" "0.00 MIL" "DRC ERROR CLASS/BOTTOM" "[Shape] Route Keepout/All ((155.0 2225.0) (480.0 2457.5))" "[Line] +V3P3S_AUD ((420.73 2394.03) (445.85 2419.15))" list(440.000000 2413.300000) nil)@@@list("bobo_dong" "2014/01/13 21:08:39" nil "S0DCOA89102" "g1t-p0jac.11")@@@nil | list("[Spacing] BOTTOM" "112.Line to Route Keepout" "0 MIL [DEFAULT]" "0 MIL" "0.00 MIL" "DRC ERROR CLASS/BOTTOM" "[Shape] Route Keepout/All ((155.0 2225.0) (480.0 2457.5))" "[Line] +V3P3S_AUD ((437.35 2410.65) (444.35 2440.28))" list(440.850000 2425.460000) nil)@@@list("bobo_dong" "2014/01/13 20:52:16" nil "S0DCOA89102" "g1t-p0jac.11")@@@nil | list("[Spacing] BOTTOM" "113.Line to Route Keepout" "0 MIL [DEFAULT]" "0 MIL" "0.00 MIL" "DRC ERROR CLASS/BOTTOM" "[Shape] Route Keepout/All ((155.0 2225.0) (480.0 2457.5))" "[Line] +V3P3S_AUD ((435.85 2377.85) (445.85 2419.15))" list(440.850000 2403.290000) nil)@@@list("bobo_dong" "2014/01/13 20:52:16" nil "S0DCOA89102" "g1t-p0jac.11")@@@nil | list("[Physical] BOTTOM" "96.Pad/Pad Direct Connect" "VIAS_PINS_ONLY [(GND_DEFAULT)]" "ALL_ALLOWED" "" "DRC ERROR CLASS/BOTTOM" "[ThruPin] GND (<uTiL>cId50<uTiL>.50) (465.23 2628.48)" "[SmdPin] GND (<uTiL>cId50<uTiL>.49) (385.73 2548.98)" list(465.230000 2628.480000) nil)@@@list("bobo_dong" "2014/01/27 15:53:49" nil "s0dcoa89102" "g1t-p0jac.11")@@@list("vincent_kuo" "2014/02/26 15:25:35" nil "VINCENT_KUO-PC" "g1t-p0jac_byt-t.14") | list("[Physical] BOTTOM" "95.Pad/Pad Direct Connect" "VIAS_PINS_ONLY [(GND_DEFAULT)]" "ALL_ALLOWED" "" "DRC ERROR CLASS/BOTTOM" "[ThruPin] GND (<uTiL>cId50<uTiL>.53) (465.23 2548.98)" "[SmdPin] GND (<uTiL>cId50<uTiL>.49) (385.73 2548.98)" list(465.230000 2548.980000) nil)@@@list("bobo_dong" "2014/01/27 15:53:48" nil "s0dcoa89102" "g1t-p0jac.11")@@@list("vincent_kuo" "2014/02/26 15:25:35" nil "VINCENT_KUO-PC" "g1t-p0jac_byt-t.14") | list("[Physical] BOTTOM" "102.Pad/Pad Direct Connect" "VIAS_PINS_ONLY [(GND_DEFAULT)]" "ALL_ALLOWED" "" "DRC ERROR CLASS/BOTTOM" "[ThruPin] GND (<uTiL>cId50<uTiL>.57) (465.23 2469.48)" "[SmdPin] GND (<uTiL>cId50<uTiL>.49) (385.73 2548.98)" list(465.230000 2469.480000) nil)@@@list("bobo_dong" "2014/01/27 15:53:55" nil "s0dcoa89102" "g1t-p0jac.11")@@@list("vincent_kuo" "2014/02/26 15:25:42" nil "VINCENT_KUO-PC" "g1t-p0jac_byt-t.14") | list("[Physical] BOTTOM" "105.Pad/Pad Direct Connect" "VIAS_PINS_ONLY [(GND_DEFAULT)]" "ALL_ALLOWED" "" "DRC ERROR CLASS/BOTTOM" "[SmdPin] GND (<uTiL>cId4105<uTiL>.2) (450.98 1888.7)" "[SmdPin] GND (<uTiL>cId3336<uTiL>.2) (465.98 1876.27)" list(465.980000 1876.270000) nil)@@@list("bobo_dong" "2014/01/27 15:53:58" nil "s0dcoa89102" "g1t-p0jac.11")@@@list("vincent_kuo" "2014/02/26 15:25:45" nil "VINCENT_KUO-PC" "g1t-p0jac_byt-t.14") | list("[Physical] BOTTOM" "1.Min Neck Width" "12.2 MIL [45OHM(12.2|3.3|4.3)]" "9 MIL" "3.20 MIL" "DRC ERROR CLASS/BOTTOM" "[Line] LDO1_EN ((493.43 2520.86) (525.43 2529.86))" " " list(509.430000 2525.360000) nil)@@@list("tank_tung" "2014/03/20 16:24:59" nil "p143000043-pc" "g1t-jct2_bdw_lpddr3.15")@@@list("vincent_kuo" "2014/03/20 16:23:06" nil "VINCENT_KUO-PC" "g1t-p0jac_byt-t.20") | list("[Physical] BOTTOM" "68.Pad/Pad Direct Connect" "VIAS_PINS_ONLY [(GND_DEFAULT)]" "ALL_ALLOWED" "" "DRC ERROR CLASS/BOTTOM" "[SmdPin] GND (<uTiL>cId4022<uTiL>.25) (638.56 882.91)" "[ThruPin] GND (<uTiL>cId4022<uTiL>.27) (596.56 924.91)" list(596.560000 924.910000) nil)@@@list("bobo_dong" "2014/01/27 15:53:20" nil "s0dcoa89102" "g1t-p0jac.11")@@@list("vincent_kuo" "2014/02/26 15:25:07" nil "VINCENT_KUO-PC" "g1t-p0jac_byt-t.14") | list("[Physical] BOTTOM" "66.Pad/Pad Direct Connect" "VIAS_PINS_ONLY [(GND_DEFAULT)]" "ALL_ALLOWED" "" "DRC ERROR CLASS/BOTTOM" "[ThruPin] GND (<uTiL>cId4022<uTiL>.29) (596.56 840.91)" "[SmdPin] GND (<uTiL>cId4022<uTiL>.25) (638.56 882.91)" list(596.560000 840.910000) nil)@@@list("bobo_dong" "2014/01/27 15:53:17" nil "s0dcoa89102" "g1t-p0jac.11")@@@list("vincent_kuo" "2014/02/26 15:25:05" nil "VINCENT_KUO-PC" "g1t-p0jac_byt-t.14") | list("[Physical] BOTTOM" "62.Pad/Pad Direct Connect" "VIAS_PINS_ONLY [DEFAULT]" "ALL_ALLOWED" "" "DRC ERROR CLASS/BOTTOM" "[SmdPin] 3VO (<uTiL>cId4098<uTiL>.1) (675.73 1723.98)" "[SmdPin] 3VO (<uTiL>cId3747<uTiL>.1) (675.73 1716.6)" list(675.730000 1723.980000) nil)@@@list("bobo_dong" "2014/01/27 15:53:11" nil "s0dcoa89102" "g1t-p0jac.11")@@@list("vincent_kuo" "2014/02/26 15:25:01" nil "VINCENT_KUO-PC" "g1t-p0jac_byt-t.14") | list("[Physical] BOTTOM" "69.Pad/Pad Direct Connect" "VIAS_PINS_ONLY [(GND_DEFAULT)]" "ALL_ALLOWED" "" "DRC ERROR CLASS/BOTTOM" "[SmdPin] GND (<uTiL>cId4022<uTiL>.25) (638.56 882.91)" "[ThruPin] GND (<uTiL>cId4022<uTiL>.26) (680.56 924.91)" list(680.560000 924.910000) nil)@@@list("bobo_dong" "2014/01/27 15:53:21" nil "s0dcoa89102" "g1t-p0jac.11")@@@list("vincent_kuo" "2014/02/26 15:25:08" nil "VINCENT_KUO-PC" "g1t-p0jac_byt-t.14") | list("[Physical] BOTTOM" "67.Pad/Pad Direct Connect" "VIAS_PINS_ONLY [(GND_DEFAULT)]" "ALL_ALLOWED" "" "DRC ERROR CLASS/BOTTOM" "[SmdPin] GND (<uTiL>cId4022<uTiL>.25) (638.56 882.91)" "[ThruPin] GND (<uTiL>cId4022<uTiL>.28) (680.56 840.91)" list(680.560000 840.910000) nil)@@@list("bobo_dong" "2014/01/27 15:53:19" nil "s0dcoa89102" "g1t-p0jac.11")@@@list("vincent_kuo" "2014/02/26 15:25:06" nil "VINCENT_KUO-PC" "g1t-p0jac_byt-t.14") | list("[Spacing] BOTTOM" "10.Thru Pin to Shape" "6 MIL [DEFAULT]" "5.68 MIL" "0.32 MIL" "DRC ERROR CLASS/BOTTOM" "[ThruPin] GND (<uTiL>cId4022<uTiL>.28) (680.56 840.91)" "[Bottom Shape] +AC_ADAPTER ((683.0 626.5) (750.0 840.0))" list(692.400000 838.940000) nil)@@@list("bobo_dong" "2014/02/25 09:08:29" nil "s0dcoa89102" "g1t-p0jac.11")@@@nil | list("[Physical] BOTTOM" "59.Pad/Pad Direct Connect" "VIAS_PINS_ONLY [DEFAULT]" "ALL_ALLOWED" "" "DRC ERROR CLASS/BOTTOM" "[SmdPin] +V1P8U_PMIC (<uTiL>cId3338<uTiL>.1) (749.0 2522.0)" "[SmdPin] +V1P8U_PMIC (<uTiL>cId3639<uTiL>.1) (741.0 2521.0)" list(749.000000 2522.000000) nil)@@@list("bobo_dong" "2014/01/27 15:53:08" nil "s0dcoa89102" "g1t-p0jac.11")@@@list("vincent_kuo" "2014/02/26 15:24:58" nil "VINCENT_KUO-PC" "g1t-p0jac_byt-t.14") | list("[Physical] BOTTOM" "56.Pad/Pad Direct Connect" "VIAS_PINS_ONLY [DEFAULT]" "ALL_ALLOWED" "" "DRC ERROR CLASS/BOTTOM" "[SmdPin] N54837978 (<uTiL>cId3337<uTiL>.1) (763.0 1586.0)" "[SmdPin] N54837978 (<uTiL>cId3635<uTiL>.1) (762.0 1593.0)" list(763.000000 1586.000000) nil)@@@list("bobo_dong" "2014/01/27 15:53:04" nil "s0dcoa89102" "g1t-p0jac.11")@@@list("vincent_kuo" "2014/02/26 15:24:41" nil "VINCENT_KUO-PC" "g1t-p0jac_byt-t.14") | list("[Physical] BOTTOM" "72.Pad/Pad Direct Connect" "VIAS_PINS_ONLY [(GND_DEFAULT)]" "ALL_ALLOWED" "" "DRC ERROR CLASS/BOTTOM" "[SmdPin] GND (<uTiL>cId4020<uTiL>.17) (1041.73 921.98)" "[ThruPin] GND (<uTiL>cId4020<uTiL>.22) (1022.04 941.67)" list(1022.040000 941.670000) nil)@@@list("bobo_dong" "2014/01/27 15:53:26" nil "s0dcoa89102" "g1t-p0jac.11")@@@list("vincent_kuo" "2014/02/26 15:25:11" nil "VINCENT_KUO-PC" "g1t-p0jac_byt-t.14") | list("[Physical] BOTTOM" "70.Pad/Pad Direct Connect" "VIAS_PINS_ONLY [(GND_DEFAULT)]" "ALL_ALLOWED" "" "DRC ERROR CLASS/BOTTOM" "[ThruPin] GND (<uTiL>cId4020<uTiL>.21) (1022.04 902.29)" "[SmdPin] GND (<uTiL>cId4020<uTiL>.17) (1041.73 921.98)" list(1022.040000 902.290000) nil)@@@list("bobo_dong" "2014/01/27 15:53:23" nil "s0dcoa89102" "g1t-p0jac.11")@@@list("vincent_kuo" "2014/02/26 15:25:09" nil "VINCENT_KUO-PC" "g1t-p0jac_byt-t.14") | list("[Physical] BOTTOM" "73.Pad/Pad Direct Connect" "VIAS_PINS_ONLY [(GND_DEFAULT)]" "ALL_ALLOWED" "" "DRC ERROR CLASS/BOTTOM" "[SmdPin] GND (<uTiL>cId4020<uTiL>.17) (1041.73 921.98)" "[ThruPin] GND (<uTiL>cId4020<uTiL>.20) (1041.73 921.98)" list(1041.730000 921.980000) nil)@@@list("bobo_dong" "2014/01/27 15:53:27" nil "s0dcoa89102" "g1t-p0jac.11")@@@list("vincent_kuo" "2014/02/26 15:25:12" nil "VINCENT_KUO-PC" "g1t-p0jac_byt-t.14") | list("[Physical] BOTTOM" "74.Pad/Pad Direct Connect" "VIAS_PINS_ONLY [(GND_DEFAULT)]" "ALL_ALLOWED" "" "DRC ERROR CLASS/BOTTOM" "[SmdPin] GND (<uTiL>cId4020<uTiL>.17) (1041.73 921.98)" "[ThruPin] GND (<uTiL>cId4020<uTiL>.19) (1061.42 941.67)" list(1061.420000 941.670000) nil)@@@list("bobo_dong" "2014/01/27 15:53:28" nil "s0dcoa89102" "g1t-p0jac.11")@@@list("vincent_kuo" "2014/02/26 15:25:13" nil "VINCENT_KUO-PC" "g1t-p0jac_byt-t.14") | list("[Physical] BOTTOM" "71.Pad/Pad Direct Connect" "VIAS_PINS_ONLY [(GND_DEFAULT)]" "ALL_ALLOWED" "" "DRC ERROR CLASS/BOTTOM" "[SmdPin] GND (<uTiL>cId4020<uTiL>.17) (1041.73 921.98)" "[ThruPin] GND (<uTiL>cId4020<uTiL>.18) (1061.42 902.29)" list(1061.420000 902.290000) nil)@@@list("bobo_dong" "2014/01/27 15:53:25" nil "s0dcoa89102" "g1t-p0jac.11")@@@list("vincent_kuo" "2014/02/26 15:25:10" nil "VINCENT_KUO-PC" "g1t-p0jac_byt-t.14") | list("[Spacing] BOTTOM" "9.SMD Pin to SMD Pin Same Net" "4 MIL [DEFAULT]" "OVERLAP" "" "DRC ERROR CLASS/BOTTOM" "[SmdPin] +VDDQ_PMIC (<uTiL>cId3717<uTiL>.1) (1132.73 1107.6)" "[SmdPin] +VDDQ_PMIC (<uTiL>cId3347<uTiL>.2) (1132.8 1119.2)" list(1120.300000 1118.600000) nil)@@@list("bobo_dong" "2014/02/25 09:08:28" nil "s0dcoa89102" "g1t-p0jac.11")@@@list("doris_chen" "2014/01/16 14:59:00" nil "JULIA_YU-PC1" "g1t-p0jac_byt-t.13-chk") | list("[Physical] BOTTOM" "61.Pad/Pad Direct Connect" "VIAS_PINS_ONLY [DEFAULT]" "ALL_ALLOWED" "" "DRC ERROR CLASS/BOTTOM" "[SmdPin] N58056974 (<uTiL>cId4214<uTiL>.1) (1132.15 170.68)" "[SmdPin] N58056974 (<uTiL>cId4190<uTiL>.2) (1138.73 169.98)" list(1138.730000 169.980000) nil)@@@list("bobo_dong" "2014/01/27 15:53:10" nil "s0dcoa89102" "g1t-p0jac.11")@@@list("vincent_kuo" "2014/02/26 15:25:00" nil "VINCENT_KUO-PC" "g1t-p0jac_byt-t.14") | list("[Spacing] BOTTOM" "8.SMD Pin to SMD Pin Same Net" "4 MIL [DEFAULT]" "OVERLAP" "" "DRC ERROR CLASS/BOTTOM" "[SmdPin] +V1P8A_PMIC (<uTiL>cId3720<uTiL>.1) (1157.11 1321.48)" "[SmdPin] +V1P8A_PMIC (<uTiL>cId3348<uTiL>.2) (1145.0 1320.0)" list(1146.110000 1307.500000) nil)@@@list("bobo_dong" "2014/02/25 09:08:27" nil "s0dcoa89102" "g1t-p0jac.11")@@@list("doris_chen" "2014/01/16 14:58:59" nil "JULIA_YU-PC1" "g1t-p0jac_byt-t.13-chk") | list("[Physical] BOTTOM" "55.Pad/Pad Direct Connect" "VIAS_PINS_ONLY [DEFAULT]" "ALL_ALLOWED" "" "DRC ERROR CLASS/BOTTOM" "[SmdPin] +VDDQ_VTT_PMIC (<uTiL>cId3695<uTiL>.1) (1150.73 1217.6)" "[SmdPin] +VDDQ_VTT_PMIC (<uTiL>cId3342<uTiL>.1) (1150.73 1206.98)" list(1150.730000 1206.980000) nil)@@@list("bobo_dong" "2014/01/27 15:53:02" nil "s0dcoa89102" "g1t-p0jac.11")@@@list("vincent_kuo" "2014/02/26 15:24:40" nil "VINCENT_KUO-PC" "g1t-p0jac_byt-t.14") | list("[Physical] BOTTOM" "54.Pad/Pad Direct Connect" "VIAS_PINS_ONLY [DEFAULT]" "ALL_ALLOWED" "" "DRC ERROR CLASS/BOTTOM" "[SmdPin] +V2P85S_PMIC (<uTiL>cId3349<uTiL>.1) (1333.73 903.98)" "[SmdPin] +V2P85S_PMIC (<uTiL>cId3721<uTiL>.1) (1342.38 904.0)" list(1333.730000 903.980000) nil)@@@list("bobo_dong" "2014/01/27 15:53:01" nil "s0dcoa89102" "g1t-p0jac.11")@@@list("vincent_kuo" "2014/02/26 15:24:39" nil "VINCENT_KUO-PC" "g1t-p0jac_byt-t.14") | list("[Spacing-SameNet] BOTTOM" "72.Line to Shape Same Net" "4 MIL [DEFAULT]" "0 MIL" "4.00 MIL" "DRC ERROR CLASS/BOTTOM" "[Line] GND ((1340.68 2912.82) (1352.3 2915.18))" "[Bottom Shape] GND ((1198.74 2722.64) (1611.43 3044.16))" list(1343.910000 2914.000000) nil)@@@list("bobo_dong" "2014/01/13 20:53:36" nil "S0DCOA89102" "g1t-p0jac.11")@@@list("vincent_kuo" "2014/01/13 22:08:21" nil "VINCENT_KUO-PC" "g1t-p0jac_byt-t.11") | list("[Spacing-SameNet] BOTTOM" "73.Line to Shape Same Net" "4 MIL [DEFAULT]" "0 MIL" "4.00 MIL" "DRC ERROR CLASS/BOTTOM" "[Line] GND ((1350.82 2891.82) (1363.18 2904.18))" "[Bottom Shape] GND ((1198.74 2722.64) (1611.43 3044.16))" list(1353.510000 2894.510000) nil)@@@list("bobo_dong" "2014/01/13 20:53:37" nil "S0DCOA89102" "g1t-p0jac.11")@@@list("vincent_kuo" "2014/01/13 22:08:21" nil "VINCENT_KUO-PC" "g1t-p0jac_byt-t.11") | list("[Spacing-SameNet] BOTTOM" "73.Line to Shape Same Net" "4 MIL [DEFAULT]" "0 MIL" "4.00 MIL" "DRC ERROR CLASS/BOTTOM" "[Line] GND ((1349.94 2912.82) (1362.18 2925.06))" "[Bottom Shape] GND ((1198.74 2722.64) (1611.43 3044.16))" list(1359.730000 2922.610000) nil)@@@list("kelly_lv" "2014/01/14 09:49:46" nil "PC-0005358" "5k-castle.105")@@@list("doris_chen" "2014/01/16 14:59:51" nil "JULIA_YU-PC1" "g1t-p0jac_byt-t.13-chk") | list("[Spacing-SameNet] BOTTOM" "72.Line to Shape Same Net" "4 MIL [DEFAULT]" "0 MIL" "4.00 MIL" "DRC ERROR CLASS/BOTTOM" "[Line] GND ((1360.82 2901.82) (1375.18 2904.18))" "[Bottom Shape] GND ((1198.74 2722.64) (1611.43 3044.16))" list(1370.900000 2903.000000) nil)@@@list("kelly_lv" "2014/01/14 09:49:47" nil "PC-0005358" "5k-castle.105")@@@list("doris_chen" "2014/01/16 14:59:50" nil "JULIA_YU-PC1" "g1t-p0jac_byt-t.13-chk") | list("[Physical] BOTTOM" "57.Pad/Pad Direct Connect" "VIAS_PINS_ONLY [DEFAULT]" "ALL_ALLOWED" "" "DRC ERROR CLASS/BOTTOM" "[SmdPin] +V3P3A_PMIC (<uTiL>cId3690<uTiL>.1) (1545.35 829.98)" "[SmdPin] +V3P3A_PMIC (<uTiL>cId3341<uTiL>.2) (1546.73 814.98)" list(1546.730000 814.980000) nil)@@@list("bobo_dong" "2014/01/27 15:53:05" nil "s0dcoa89102" "g1t-p0jac.11")@@@list("vincent_kuo" "2014/02/26 15:24:56" nil "VINCENT_KUO-PC" "g1t-p0jac_byt-t.14") | list("[Physical] BOTTOM" "52.Pad/Pad Direct Connect" "VIAS_PINS_ONLY [DEFAULT]" "ALL_ALLOWED" "" "DRC ERROR CLASS/BOTTOM" "[SmdPin] +V5P0S_PMIC (<uTiL>cId3944<uTiL>.1) (1730.62 833.0)" "[SmdPin] +V5P0S_PMIC (<uTiL>cId3346<uTiL>.2) (1737.73 836.98)" list(1737.730000 836.980000) nil)@@@list("bobo_dong" "2014/01/27 15:52:58" nil "s0dcoa89102" "g1t-p0jac.11")@@@list("vincent_kuo" "2014/02/26 15:24:37" nil "VINCENT_KUO-PC" "g1t-p0jac_byt-t.14") | list("[Physical] BOTTOM" "28.Pad/Pad Direct Connect" "VIAS_PINS_ONLY [100OHM(DP_#1/#2/5/200)]" "ALL_ALLOWED" "" "DRC ERROR CLASS/BOTTOM" "[SmdPin] EDP_LVDS_1+_R (<uTiL>cId3868<uTiL>.2) (1820.09 286.78)" "[SmdPin] EDP_LVDS_1+_R (<uTiL>cId3904<uTiL>.2) (1818.12 284.81)" list(1818.120000 284.810000) nil)@@@list("bobo_dong" "2014/01/27 15:52:27" nil "s0dcoa89102" "g1t-p0jac.11")@@@list("vincent_kuo" "2014/02/26 15:24:10" nil "VINCENT_KUO-PC" "g1t-p0jac_byt-t.14") | list("[Physical] BOTTOM" "31.Pad/Pad Direct Connect" "VIAS_PINS_ONLY [100OHM(DP_#1/#2/5/200)]" "ALL_ALLOWED" "" "DRC ERROR CLASS/BOTTOM" "[SmdPin] EDP_LVDS_1-_R (<uTiL>cId3868<uTiL>.4) (1820.09 261.18)" "[SmdPin] EDP_LVDS_1-_R (<uTiL>cId3904<uTiL>.3) (1818.12 263.15)" list(1818.120000 263.150000) nil)@@@list("bobo_dong" "2014/01/27 15:52:32" nil "s0dcoa89102" "g1t-p0jac.11")@@@list("vincent_kuo" "2014/02/26 15:24:14" nil "VINCENT_KUO-PC" "g1t-p0jac_byt-t.14") | list("[Physical] BOTTOM" "26.Pad/Pad Direct Connect" "VIAS_PINS_ONLY [100OHM(DP_#1/#2/5/200)]" "ALL_ALLOWED" "" "DRC ERROR CLASS/BOTTOM" "[SmdPin] EDP_LVDS_0-_R (<uTiL>cId3869<uTiL>.2) (1820.09 231.78)" "[SmdPin] EDP_LVDS_0-_R (<uTiL>cId3906<uTiL>.2) (1818.12 229.81)" list(1818.120000 229.810000) nil)@@@list("bobo_dong" "2014/01/27 15:52:25" nil "s0dcoa89102" "g1t-p0jac.11")@@@list("vincent_kuo" "2014/02/26 15:24:08" nil "VINCENT_KUO-PC" "g1t-p0jac_byt-t.14") | list("[Physical] BOTTOM" "16.Pad/Pad Direct Connect" "VIAS_PINS_ONLY [100OHM(DP_#1/#2/5/200)]" "ALL_ALLOWED" "" "DRC ERROR CLASS/BOTTOM" "[SmdPin] EDP_LVDS_0+_R (<uTiL>cId3869<uTiL>.4) (1820.09 206.18)" "[SmdPin] EDP_LVDS_0+_R (<uTiL>cId3906<uTiL>.3) (1818.12 208.15)" list(1818.120000 208.150000) nil)@@@list("bobo_dong" "2014/01/27 15:52:14" nil "s0dcoa89102" "g1t-p0jac.11")@@@list("vincent_kuo" "2014/02/26 15:23:55" nil "VINCENT_KUO-PC" "g1t-p0jac_byt-t.14") | list("[Physical] BOTTOM" "19.Pad/Pad Direct Connect" "VIAS_PINS_ONLY [100OHM(DP_#1/#2/5/200)]" "ALL_ALLOWED" "" "DRC ERROR CLASS/BOTTOM" "[SmdPin] EDP_LVDS_2-_R (<uTiL>cId3867<uTiL>.2) (1820.09 178.78)" "[SmdPin] EDP_LVDS_2-_R (<uTiL>cId3903<uTiL>.2) (1818.12 176.81)" list(1818.120000 176.810000) nil)@@@list("bobo_dong" "2014/01/27 15:52:17" nil "s0dcoa89102" "g1t-p0jac.11")@@@list("vincent_kuo" "2014/02/26 15:23:59" nil "VINCENT_KUO-PC" "g1t-p0jac_byt-t.14") | list("[Physical] BOTTOM" "20.Pad/Pad Direct Connect" "VIAS_PINS_ONLY [100OHM(DP_#1/#2/5/200)]" "ALL_ALLOWED" "" "DRC ERROR CLASS/BOTTOM" "[SmdPin] EDP_LVDS_2+_R (<uTiL>cId3867<uTiL>.4) (1820.09 153.18)" "[SmdPin] EDP_LVDS_2+_R (<uTiL>cId3903<uTiL>.3) (1818.12 155.15)" list(1818.120000 155.150000) nil)@@@list("bobo_dong" "2014/01/27 15:52:18" nil "s0dcoa89102" "g1t-p0jac.11")@@@list("vincent_kuo" "2014/02/26 15:24:01" nil "VINCENT_KUO-PC" "g1t-p0jac_byt-t.14") | list("[Physical] BOTTOM" "22.Pad/Pad Direct Connect" "VIAS_PINS_ONLY [100OHM(DP_#1/#2/5/200)]" "ALL_ALLOWED" "" "DRC ERROR CLASS/BOTTOM" "[SmdPin] EDP_LVDS_C+_R (<uTiL>cId3865<uTiL>.2) (1820.09 123.78)" "[SmdPin] EDP_LVDS_C+_R (<uTiL>cId3905<uTiL>.2) (1818.12 121.81)" list(1818.120000 121.810000) nil)@@@list("bobo_dong" "2014/01/27 15:52:20" nil "s0dcoa89102" "g1t-p0jac.11")@@@list("vincent_kuo" "2014/02/26 15:24:04" nil "VINCENT_KUO-PC" "g1t-p0jac_byt-t.14") | list("[Physical] BOTTOM" "33.Pad/Pad Direct Connect" "VIAS_PINS_ONLY [100OHM(DP_#1/#2/5/200)]" "ALL_ALLOWED" "" "DRC ERROR CLASS/BOTTOM" "[SmdPin] EDP_LVDS_C-_R (<uTiL>cId3865<uTiL>.4) (1820.09 98.18)" "[SmdPin] EDP_LVDS_C-_R (<uTiL>cId3905<uTiL>.3) (1818.12 100.15)" list(1818.120000 100.150000) nil)@@@list("bobo_dong" "2014/01/27 15:52:34" nil "s0dcoa89102" "g1t-p0jac.11")@@@list("vincent_kuo" "2014/02/26 15:24:16" nil "VINCENT_KUO-PC" "g1t-p0jac_byt-t.14") | list("[Physical] BOTTOM" "24.Pad/Pad Direct Connect" "VIAS_PINS_ONLY [100OHM(DP_#1/#2/5/200)]" "ALL_ALLOWED" "" "DRC ERROR CLASS/BOTTOM" "[SmdPin] EDP_LVDS_3+_R (<uTiL>cId3866<uTiL>.2) (1821.09 69.78)" "[SmdPin] EDP_LVDS_3+_R (<uTiL>cId3902<uTiL>.2) (1819.12 67.81)" list(1819.120000 67.810000) nil)@@@list("bobo_dong" "2014/01/27 15:52:23" nil "s0dcoa89102" "g1t-p0jac.11")@@@list("vincent_kuo" "2014/02/26 15:24:06" nil "VINCENT_KUO-PC" "g1t-p0jac_byt-t.14") | list("[Physical] BOTTOM" "35.Pad/Pad Direct Connect" "VIAS_PINS_ONLY [100OHM(DP_#1/#2/5/200)]" "ALL_ALLOWED" "" "DRC ERROR CLASS/BOTTOM" "[SmdPin] EDP_LVDS_3-_R (<uTiL>cId3866<uTiL>.4) (1821.09 44.18)" "[SmdPin] EDP_LVDS_3-_R (<uTiL>cId3902<uTiL>.3) (1819.12 46.15)" list(1819.120000 46.150000) nil)@@@list("bobo_dong" "2014/01/27 15:52:36" nil "s0dcoa89102" "g1t-p0jac.11")@@@list("vincent_kuo" "2014/02/26 15:24:19" nil "VINCENT_KUO-PC" "g1t-p0jac_byt-t.14") | list("[Physical] BOTTOM" "29.Pad/Pad Direct Connect" "VIAS_PINS_ONLY [100OHM(DP_#1/#2/5/200)]" "ALL_ALLOWED" "" "DRC ERROR CLASS/BOTTOM" "[SmdPin] TB0P (<uTiL>cId3868<uTiL>.1) (1865.37 286.78)" "[SmdPin] TB0P (<uTiL>cId3904<uTiL>.1) (1867.34 284.81)" list(1867.340000 284.810000) nil)@@@list("bobo_dong" "2014/01/27 15:52:28" nil "s0dcoa89102" "g1t-p0jac.11")@@@list("vincent_kuo" "2014/02/26 15:24:12" nil "VINCENT_KUO-PC" "g1t-p0jac_byt-t.14") | list("[Physical] BOTTOM" "30.Pad/Pad Direct Connect" "VIAS_PINS_ONLY [100OHM(DP_#1/#2/5/200)]" "ALL_ALLOWED" "" "DRC ERROR CLASS/BOTTOM" "[SmdPin] TB0N (<uTiL>cId3868<uTiL>.3) (1865.37 261.18)" "[SmdPin] TB0N (<uTiL>cId3904<uTiL>.4) (1867.34 263.15)" list(1867.340000 263.150000) nil)@@@list("bobo_dong" "2014/01/27 15:52:29" nil "s0dcoa89102" "g1t-p0jac.11")@@@list("vincent_kuo" "2014/02/26 15:24:13" nil "VINCENT_KUO-PC" "g1t-p0jac_byt-t.14") | list("[Physical] BOTTOM" "27.Pad/Pad Direct Connect" "VIAS_PINS_ONLY [100OHM(DP_#1/#2/5/200)]" "ALL_ALLOWED" "" "DRC ERROR CLASS/BOTTOM" "[SmdPin] TA0N (<uTiL>cId3869<uTiL>.1) (1865.37 231.78)" "[SmdPin] TA0N (<uTiL>cId3906<uTiL>.1) (1867.34 229.81)" list(1867.340000 229.810000) nil)@@@list("bobo_dong" "2014/01/27 15:52:26" nil "s0dcoa89102" "g1t-p0jac.11")@@@list("vincent_kuo" "2014/02/26 15:24:09" nil "VINCENT_KUO-PC" "g1t-p0jac_byt-t.14") | list("[Physical] BOTTOM" "17.Pad/Pad Direct Connect" "VIAS_PINS_ONLY [100OHM(DP_#1/#2/5/200)]" "ALL_ALLOWED" "" "DRC ERROR CLASS/BOTTOM" "[SmdPin] TA0P (<uTiL>cId3869<uTiL>.3) (1865.37 206.18)" "[SmdPin] TA0P (<uTiL>cId3906<uTiL>.4) (1867.34 208.15)" list(1867.340000 208.150000) nil)@@@list("bobo_dong" "2014/01/27 15:52:15" nil "s0dcoa89102" "g1t-p0jac.11")@@@list("vincent_kuo" "2014/02/26 15:23:57" nil "VINCENT_KUO-PC" "g1t-p0jac_byt-t.14") | list("[Physical] BOTTOM" "18.Pad/Pad Direct Connect" "VIAS_PINS_ONLY [100OHM(DP_#1/#2/5/200)]" "ALL_ALLOWED" "" "DRC ERROR CLASS/BOTTOM" "[SmdPin] TC0N (<uTiL>cId3867<uTiL>.1) (1865.37 178.78)" "[SmdPin] TC0N (<uTiL>cId3903<uTiL>.1) (1867.34 176.81)" list(1867.340000 176.810000) nil)@@@list("bobo_dong" "2014/01/27 15:52:16" nil "s0dcoa89102" "g1t-p0jac.11")@@@list("vincent_kuo" "2014/02/26 15:23:58" nil "VINCENT_KUO-PC" "g1t-p0jac_byt-t.14") | list("[Physical] BOTTOM" "21.Pad/Pad Direct Connect" "VIAS_PINS_ONLY [100OHM(DP_#1/#2/5/200)]" "ALL_ALLOWED" "" "DRC ERROR CLASS/BOTTOM" "[SmdPin] TC0P (<uTiL>cId3867<uTiL>.3) (1865.37 153.18)" "[SmdPin] TC0P (<uTiL>cId3903<uTiL>.4) (1867.34 155.15)" list(1867.340000 155.150000) nil)@@@list("bobo_dong" "2014/01/27 15:52:19" nil "s0dcoa89102" "g1t-p0jac.11")@@@list("vincent_kuo" "2014/02/26 15:24:02" nil "VINCENT_KUO-PC" "g1t-p0jac_byt-t.14") | list("[Physical] BOTTOM" "23.Pad/Pad Direct Connect" "VIAS_PINS_ONLY [100OHM(DP_#1/#2/5/200)]" "ALL_ALLOWED" "" "DRC ERROR CLASS/BOTTOM" "[SmdPin] TCK0P (<uTiL>cId3865<uTiL>.1) (1865.37 123.78)" "[SmdPin] TCK0P (<uTiL>cId3905<uTiL>.1) (1867.34 121.81)" list(1867.340000 121.810000) nil)@@@list("bobo_dong" "2014/01/27 15:52:21" nil "s0dcoa89102" "g1t-p0jac.11")@@@list("vincent_kuo" "2014/02/26 15:24:05" nil "VINCENT_KUO-PC" "g1t-p0jac_byt-t.14") | list("[Physical] BOTTOM" "32.Pad/Pad Direct Connect" "VIAS_PINS_ONLY [100OHM(DP_#1/#2/5/200)]" "ALL_ALLOWED" "" "DRC ERROR CLASS/BOTTOM" "[SmdPin] TCK0N (<uTiL>cId3865<uTiL>.3) (1865.37 98.18)" "[SmdPin] TCK0N (<uTiL>cId3905<uTiL>.4) (1867.34 100.15)" list(1867.340000 100.150000) nil)@@@list("bobo_dong" "2014/01/27 15:52:33" nil "s0dcoa89102" "g1t-p0jac.11")@@@list("vincent_kuo" "2014/02/26 15:24:15" nil "VINCENT_KUO-PC" "g1t-p0jac_byt-t.14") | list("[Physical] BOTTOM" "25.Pad/Pad Direct Connect" "VIAS_PINS_ONLY [100OHM(DP_#1/#2/5/200)]" "ALL_ALLOWED" "" "DRC ERROR CLASS/BOTTOM" "[SmdPin] TD0P (<uTiL>cId3866<uTiL>.1) (1866.37 69.78)" "[SmdPin] TD0P (<uTiL>cId3902<uTiL>.1) (1868.34 67.81)" list(1868.340000 67.810000) nil)@@@list("bobo_dong" "2014/01/27 15:52:24" nil "s0dcoa89102" "g1t-p0jac.11")@@@list("vincent_kuo" "2014/02/26 15:24:07" nil "VINCENT_KUO-PC" "g1t-p0jac_byt-t.14") | list("[Physical] BOTTOM" "34.Pad/Pad Direct Connect" "VIAS_PINS_ONLY [100OHM(DP_#1/#2/5/200)]" "ALL_ALLOWED" "" "DRC ERROR CLASS/BOTTOM" "[SmdPin] TD0N (<uTiL>cId3866<uTiL>.3) (1866.37 44.18)" "[SmdPin] TD0N (<uTiL>cId3902<uTiL>.4) (1868.34 46.15)" list(1868.340000 46.150000) nil)@@@list("bobo_dong" "2014/01/27 15:52:35" nil "s0dcoa89102" "g1t-p0jac.11")@@@list("vincent_kuo" "2014/02/26 15:24:18" nil "VINCENT_KUO-PC" "g1t-p0jac_byt-t.14") | list("[Physical] BOTTOM" "83.Pad/Pad Direct Connect" "VIAS_PINS_ONLY [(GND_DEFAULT)]" "ALL_ALLOWED" "" "DRC ERROR CLASS/BOTTOM" "[SmdPin] GND (<uTiL>cId4044<uTiL>.49) (2045.73 653.98)" "[ThruPin] GND (<uTiL>cId4044<uTiL>.65) (1986.67 713.04)" list(1986.670000 713.040000) nil)@@@list("bobo_dong" "2014/01/27 15:53:36" nil "s0dcoa89102" "g1t-p0jac.11")@@@list("vincent_kuo" "2014/02/26 15:25:23" nil "VINCENT_KUO-PC" "g1t-p0jac_byt-t.14") | list("[Physical] BOTTOM" "84.Pad/Pad Direct Connect" "VIAS_PINS_ONLY [(GND_DEFAULT)]" "ALL_ALLOWED" "" "DRC ERROR CLASS/BOTTOM" "[SmdPin] GND (<uTiL>cId4044<uTiL>.49) (2045.73 653.98)" "[ThruPin] GND (<uTiL>cId4044<uTiL>.58) (1986.67 673.67)" list(1986.670000 673.670000) nil)@@@list("bobo_dong" "2014/01/27 15:53:37" nil "s0dcoa89102" "g1t-p0jac.11")@@@list("vincent_kuo" "2014/02/26 15:25:24" nil "VINCENT_KUO-PC" "g1t-p0jac_byt-t.14") | list("[Physical] BOTTOM" "76.Pad/Pad Direct Connect" "VIAS_PINS_ONLY [(GND_DEFAULT)]" "ALL_ALLOWED" "" "DRC ERROR CLASS/BOTTOM" "[SmdPin] GND (<uTiL>cId4044<uTiL>.49) (2045.73 653.98)" "[ThruPin] GND (<uTiL>cId4044<uTiL>.57) (1986.67 634.29)" list(1986.670000 634.290000) nil)@@@list("bobo_dong" "2014/01/27 15:53:30" nil "s0dcoa89102" "g1t-p0jac.11")@@@list("vincent_kuo" "2014/02/26 15:25:15" nil "VINCENT_KUO-PC" "g1t-p0jac_byt-t.14") | list("[Physical] BOTTOM" "75.Pad/Pad Direct Connect" "VIAS_PINS_ONLY [(GND_DEFAULT)]" "ALL_ALLOWED" "" "DRC ERROR CLASS/BOTTOM" "[ThruPin] GND (<uTiL>cId4044<uTiL>.50) (1986.67 594.92)" "[SmdPin] GND (<uTiL>cId4044<uTiL>.49) (2045.73 653.98)" list(1986.670000 594.920000) nil)@@@list("bobo_dong" "2014/01/27 15:53:30" nil "s0dcoa89102" "g1t-p0jac.11")@@@list("vincent_kuo" "2014/02/26 15:25:14" nil "VINCENT_KUO-PC" "g1t-p0jac_byt-t.14") | list("[Physical] BOTTOM" "85.Pad/Pad Direct Connect" "VIAS_PINS_ONLY [(GND_DEFAULT)]" "ALL_ALLOWED" "" "DRC ERROR CLASS/BOTTOM" "[SmdPin] GND (<uTiL>cId4044<uTiL>.49) (2045.73 653.98)" "[ThruPin] GND (<uTiL>cId4044<uTiL>.64) (2026.04 713.04)" list(2026.040000 713.040000) nil)@@@list("bobo_dong" "2014/01/27 15:53:38" nil "s0dcoa89102" "g1t-p0jac.11")@@@list("vincent_kuo" "2014/02/26 15:25:26" nil "VINCENT_KUO-PC" "g1t-p0jac_byt-t.14") | list("[Physical] BOTTOM" "90.Pad/Pad Direct Connect" "VIAS_PINS_ONLY [(GND_DEFAULT)]" "ALL_ALLOWED" "" "DRC ERROR CLASS/BOTTOM" "[SmdPin] GND (<uTiL>cId4044<uTiL>.49) (2045.73 653.98)" "[ThruPin] GND (<uTiL>cId4044<uTiL>.59) (2026.04 673.67)" list(2026.040000 673.670000) nil)@@@list("bobo_dong" "2014/01/27 15:53:43" nil "s0dcoa89102" "g1t-p0jac.11")@@@list("vincent_kuo" "2014/02/26 15:25:30" nil "VINCENT_KUO-PC" "g1t-p0jac_byt-t.14") | list("[Physical] BOTTOM" "82.Pad/Pad Direct Connect" "VIAS_PINS_ONLY [(GND_DEFAULT)]" "ALL_ALLOWED" "" "DRC ERROR CLASS/BOTTOM" "[SmdPin] GND (<uTiL>cId4044<uTiL>.49) (2045.73 653.98)" "[ThruPin] GND (<uTiL>cId4044<uTiL>.56) (2026.04 634.29)" list(2026.040000 634.290000) nil)@@@list("bobo_dong" "2014/01/27 15:53:35" nil "s0dcoa89102" "g1t-p0jac.11")@@@list("vincent_kuo" "2014/02/26 15:25:22" nil "VINCENT_KUO-PC" "g1t-p0jac_byt-t.14") | list("[Physical] BOTTOM" "81.Pad/Pad Direct Connect" "VIAS_PINS_ONLY [(GND_DEFAULT)]" "ALL_ALLOWED" "" "DRC ERROR CLASS/BOTTOM" "[SmdPin] GND (<uTiL>cId4044<uTiL>.49) (2045.73 653.98)" "[ThruPin] GND (<uTiL>cId4044<uTiL>.51) (2026.04 594.92)" list(2026.040000 594.920000) nil)@@@list("bobo_dong" "2014/01/27 15:53:34" nil "s0dcoa89102" "g1t-p0jac.11")@@@list("vincent_kuo" "2014/02/26 15:25:21" nil "VINCENT_KUO-PC" "g1t-p0jac_byt-t.14") | list("[Physical] BOTTOM" "2.Min Neck Width" "12.2 MIL [45OHM(12.2|3.3|4.3)]" "9 MIL" "3.20 MIL" "DRC ERROR CLASS/BOTTOM" "[Line] EC_CH_GA_SDA ((1989.5 2599.45) (2071.99 2608.45))" " " list(2030.740000 2603.950000) nil)@@@list("tank_tung" "2014/03/20 16:25:00" nil "p143000043-pc" "g1t-jct2_bdw_lpddr3.15")@@@list("vincent_kuo" "2014/03/20 16:23:08" nil "VINCENT_KUO-PC" "g1t-p0jac_byt-t.20") | list("[Physical] BOTTOM" "65.Pad/Pad Direct Connect" "VIAS_PINS_ONLY [(GND_DEFAULT)]" "ALL_ALLOWED" "" "DRC ERROR CLASS/BOTTOM" "[SmdPin] GND (<uTiL>cId3741<uTiL>.2) (2061.11 1940.98)" "[SmdPin] GND (<uTiL>cId3345<uTiL>.2) (2061.0 1955.0)" list(2061.000000 1955.000000) nil)@@@list("bobo_dong" "2014/01/27 15:53:15" nil "s0dcoa89102" "g1t-p0jac.11")@@@list("vincent_kuo" "2014/02/26 15:25:03" nil "VINCENT_KUO-PC" "g1t-p0jac_byt-t.14") | list("[Physical] BOTTOM" "86.Pad/Pad Direct Connect" "VIAS_PINS_ONLY [(GND_DEFAULT)]" "ALL_ALLOWED" "" "DRC ERROR CLASS/BOTTOM" "[SmdPin] GND (<uTiL>cId4044<uTiL>.49) (2045.73 653.98)" "[ThruPin] GND (<uTiL>cId4044<uTiL>.63) (2065.42 713.04)" list(2065.420000 713.040000) nil)@@@list("bobo_dong" "2014/01/27 15:53:39" nil "s0dcoa89102" "g1t-p0jac.11")@@@list("vincent_kuo" "2014/02/26 15:25:27" nil "VINCENT_KUO-PC" "g1t-p0jac_byt-t.14") | list("[Physical] BOTTOM" "89.Pad/Pad Direct Connect" "VIAS_PINS_ONLY [(GND_DEFAULT)]" "ALL_ALLOWED" "" "DRC ERROR CLASS/BOTTOM" "[SmdPin] GND (<uTiL>cId4044<uTiL>.49) (2045.73 653.98)" "[ThruPin] GND (<uTiL>cId4044<uTiL>.60) (2065.42 673.67)" list(2065.420000 673.670000) nil)@@@list("bobo_dong" "2014/01/27 15:53:42" nil "s0dcoa89102" "g1t-p0jac.11")@@@list("vincent_kuo" "2014/02/26 15:25:30" nil "VINCENT_KUO-PC" "g1t-p0jac_byt-t.14") | list("[Physical] BOTTOM" "77.Pad/Pad Direct Connect" "VIAS_PINS_ONLY [(GND_DEFAULT)]" "ALL_ALLOWED" "" "DRC ERROR CLASS/BOTTOM" "[SmdPin] GND (<uTiL>cId4044<uTiL>.49) (2045.73 653.98)" "[ThruPin] GND (<uTiL>cId4044<uTiL>.55) (2065.42 634.29)" list(2065.420000 634.290000) nil)@@@list("bobo_dong" "2014/01/27 15:53:31" nil "s0dcoa89102" "g1t-p0jac.11")@@@list("vincent_kuo" "2014/02/26 15:25:16" nil "VINCENT_KUO-PC" "g1t-p0jac_byt-t.14") | list("[Physical] BOTTOM" "80.Pad/Pad Direct Connect" "VIAS_PINS_ONLY [(GND_DEFAULT)]" "ALL_ALLOWED" "" "DRC ERROR CLASS/BOTTOM" "[SmdPin] GND (<uTiL>cId4044<uTiL>.49) (2045.73 653.98)" "[ThruPin] GND (<uTiL>cId4044<uTiL>.52) (2065.42 594.92)" list(2065.420000 594.920000) nil)@@@list("bobo_dong" "2014/01/27 15:53:34" nil "s0dcoa89102" "g1t-p0jac.11")@@@list("vincent_kuo" "2014/02/26 15:25:20" nil "VINCENT_KUO-PC" "g1t-p0jac_byt-t.14") | list("[Physical] BOTTOM" "106.Pad/Pad Direct Connect" "VIAS_PINS_ONLY [PWR(20)]" "ALL_ALLOWED" "" "DRC ERROR CLASS/BOTTOM" "[SmdPin] +V1P05S_PMIC (<uTiL>cId3712<uTiL>.1) (2086.28 1315.15)" "[SmdPin] +V1P05S_PMIC (<uTiL>cId3350<uTiL>.1) (2091.73 1316.98)" list(2091.730000 1316.980000) nil)@@@list("bobo_dong" "2014/01/27 15:54:01" nil "s0dcoa89102" "g1t-p0jac.11")@@@list("vincent_kuo" "2014/02/26 15:25:46" nil "VINCENT_KUO-PC" "g1t-p0jac_byt-t.14") | list("[Physical] BOTTOM" "87.Pad/Pad Direct Connect" "VIAS_PINS_ONLY [(GND_DEFAULT)]" "ALL_ALLOWED" "" "DRC ERROR CLASS/BOTTOM" "[SmdPin] GND (<uTiL>cId4044<uTiL>.49) (2045.73 653.98)" "[ThruPin] GND (<uTiL>cId4044<uTiL>.62) (2104.79 713.04)" list(2104.790000 713.040000) nil)@@@list("bobo_dong" "2014/01/27 15:53:40" nil "s0dcoa89102" "g1t-p0jac.11")@@@list("vincent_kuo" "2014/02/26 15:25:28" nil "VINCENT_KUO-PC" "g1t-p0jac_byt-t.14") | list("[Physical] BOTTOM" "88.Pad/Pad Direct Connect" "VIAS_PINS_ONLY [(GND_DEFAULT)]" "ALL_ALLOWED" "" "DRC ERROR CLASS/BOTTOM" "[SmdPin] GND (<uTiL>cId4044<uTiL>.49) (2045.73 653.98)" "[ThruPin] GND (<uTiL>cId4044<uTiL>.61) (2104.79 673.67)" list(2104.790000 673.670000) nil)@@@list("bobo_dong" "2014/01/27 15:53:41" nil "s0dcoa89102" "g1t-p0jac.11")@@@list("vincent_kuo" "2014/02/26 15:25:29" nil "VINCENT_KUO-PC" "g1t-p0jac_byt-t.14") | list("[Physical] BOTTOM" "78.Pad/Pad Direct Connect" "VIAS_PINS_ONLY [(GND_DEFAULT)]" "ALL_ALLOWED" "" "DRC ERROR CLASS/BOTTOM" "[SmdPin] GND (<uTiL>cId4044<uTiL>.49) (2045.73 653.98)" "[ThruPin] GND (<uTiL>cId4044<uTiL>.54) (2104.79 634.29)" list(2104.790000 634.290000) nil)@@@list("bobo_dong" "2014/01/27 15:53:32" nil "s0dcoa89102" "g1t-p0jac.11")@@@list("vincent_kuo" "2014/02/26 15:25:18" nil "VINCENT_KUO-PC" "g1t-p0jac_byt-t.14") | list("[Physical] BOTTOM" "79.Pad/Pad Direct Connect" "VIAS_PINS_ONLY [(GND_DEFAULT)]" "ALL_ALLOWED" "" "DRC ERROR CLASS/BOTTOM" "[SmdPin] GND (<uTiL>cId4044<uTiL>.49) (2045.73 653.98)" "[ThruPin] GND (<uTiL>cId4044<uTiL>.53) (2104.79 594.92)" list(2104.790000 594.920000) nil)@@@list("bobo_dong" "2014/01/27 15:53:33" nil "s0dcoa89102" "g1t-p0jac.11")@@@list("vincent_kuo" "2014/02/26 15:25:19" nil "VINCENT_KUO-PC" "g1t-p0jac_byt-t.14") | list("[Physical] BOTTOM" "64.Pad/Pad Direct Connect" "VIAS_PINS_ONLY [DEFAULT]" "ALL_ALLOWED" "" "DRC ERROR CLASS/BOTTOM" "[SmdPin] +V1P0A_PMIC (<uTiL>cId3351<uTiL>.1) (2142.0 1144.0)" "[SmdPin] +V1P0A_PMIC (<uTiL>cId3726<uTiL>.1) (2141.73 1151.36)" list(2142.000000 1144.000000) nil)@@@list("bobo_dong" "2014/01/27 15:53:14" nil "s0dcoa89102" "g1t-p0jac.11")@@@list("vincent_kuo" "2014/02/26 15:25:03" nil "VINCENT_KUO-PC" "g1t-p0jac_byt-t.14") | list("[Physical] BOTTOM" "58.Pad/Pad Direct Connect" "VIAS_PINS_ONLY [DEFAULT]" "ALL_ALLOWED" "" "DRC ERROR CLASS/BOTTOM" "[SmdPin] +V1P0S_PMIC (<uTiL>cId3495<uTiL>.1) (2210.73 957.98)" "[SmdPin] +V1P0S_PMIC (<uTiL>cId3340<uTiL>.1) (2203.73 960.98)" list(2203.730000 960.980000) nil)@@@list("bobo_dong" "2014/01/27 15:53:07" nil "s0dcoa89102" "g1t-p0jac.11")@@@list("vincent_kuo" "2014/02/26 15:24:57" nil "VINCENT_KUO-PC" "g1t-p0jac_byt-t.14") | list("[Physical] BOTTOM" "92.Pad/Pad Direct Connect" "VIAS_PINS_ONLY [(GND_DEFAULT)]" "ALL_ALLOWED" "" "DRC ERROR CLASS/BOTTOM" "[SmdPin] GND (<uTiL>cId4027<uTiL>.17) (2353.0 1655.0)" "[ThruPin] GND (<uTiL>cId4027<uTiL>.18) (2313.0 1695.0)" list(2313.000000 1695.000000) nil)@@@list("bobo_dong" "2014/01/27 15:53:45" nil "s0dcoa89102" "g1t-p0jac.11")@@@list("vincent_kuo" "2014/02/26 15:25:32" nil "VINCENT_KUO-PC" "g1t-p0jac_byt-t.14") | list("[Physical] BOTTOM" "91.Pad/Pad Direct Connect" "VIAS_PINS_ONLY [(GND_DEFAULT)]" "ALL_ALLOWED" "" "DRC ERROR CLASS/BOTTOM" "[ThruPin] GND (<uTiL>cId4027<uTiL>.19) (2313.0 1615.0)" "[SmdPin] GND (<uTiL>cId4027<uTiL>.17) (2353.0 1655.0)" list(2313.000000 1615.000000) nil)@@@list("bobo_dong" "2014/01/27 15:53:44" nil "s0dcoa89102" "g1t-p0jac.11")@@@list("vincent_kuo" "2014/02/26 15:25:31" nil "VINCENT_KUO-PC" "g1t-p0jac_byt-t.14") | list("[Spacing] BOTTOM" "76.Shape to Route Keepout" "0 MIL [DEFAULT]" "0 MIL" "0.00 MIL" "DRC ERROR CLASS/BOTTOM" "[Shape] Route Keepout/All ((2340.76 2096.28) (2462.38 2139.9))" "[Bottom Shape] GND ((-679.11 -19.37) (3281.09 4854.01))" list(2362.570000 2139.900000) nil)@@@list("bobo_dong" "2014/01/13 20:49:10" nil "S0DCOA89102" "g1t-p0jac.11")@@@nil | list("[Physical] BOTTOM" "94.Pad/Pad Direct Connect" "VIAS_PINS_ONLY [(GND_DEFAULT)]" "ALL_ALLOWED" "" "DRC ERROR CLASS/BOTTOM" "[SmdPin] GND (<uTiL>cId4027<uTiL>.17) (2353.0 1655.0)" "[ThruPin] GND (<uTiL>cId4027<uTiL>.20) (2393.0 1695.0)" list(2393.000000 1695.000000) nil)@@@list("bobo_dong" "2014/01/27 15:53:47" nil "s0dcoa89102" "g1t-p0jac.11")@@@list("vincent_kuo" "2014/02/26 15:25:34" nil "VINCENT_KUO-PC" "g1t-p0jac_byt-t.14") | list("[Physical] BOTTOM" "93.Pad/Pad Direct Connect" "VIAS_PINS_ONLY [(GND_DEFAULT)]" "ALL_ALLOWED" "" "DRC ERROR CLASS/BOTTOM" "[SmdPin] GND (<uTiL>cId4027<uTiL>.17) (2353.0 1655.0)" "[ThruPin] GND (<uTiL>cId4027<uTiL>.21) (2393.0 1615.0)" list(2393.000000 1615.000000) nil)@@@list("bobo_dong" "2014/01/27 15:53:46" nil "s0dcoa89102" "g1t-p0jac.11")@@@list("vincent_kuo" "2014/02/26 15:25:33" nil "VINCENT_KUO-PC" "g1t-p0jac_byt-t.14") | list("[Physical] BOTTOM" "63.Pad/Pad Direct Connect" "VIAS_PINS_ONLY [DEFAULT]" "ALL_ALLOWED" "" "DRC ERROR CLASS/BOTTOM" "[SmdPin] +5VO (<uTiL>cId3913<uTiL>.1) (2440.0 1794.5)" "[SmdPin] +5VO (<uTiL>cId3352<uTiL>.1) (2442.0 1826.0)" list(2442.000000 1826.000000) nil)@@@list("bobo_dong" "2014/01/27 15:53:13" nil "s0dcoa89102" "g1t-p0jac.11")@@@list("vincent_kuo" "2014/02/26 15:25:01" nil "VINCENT_KUO-PC" "g1t-p0jac_byt-t.14") | list("[Physical] BOTTOM" "60.Pad/Pad Direct Connect" "VIAS_PINS_ONLY [DEFAULT]" "ALL_ALLOWED" "" "DRC ERROR CLASS/BOTTOM" "[SmdPin] +V1P0SX_PMIC (<uTiL>cId3640<uTiL>.1) (2449.73 956.98)" "[SmdPin] +V1P0SX_PMIC (<uTiL>cId3339<uTiL>.1) (2453.73 951.98)" list(2453.730000 951.980000) nil)@@@list("bobo_dong" "2014/01/27 15:53:09" nil "s0dcoa89102" "g1t-p0jac.11")@@@list("vincent_kuo" "2014/02/26 15:24:59" nil "VINCENT_KUO-PC" "g1t-p0jac_byt-t.14") | list("[Spacing] BOTTOM" "79.Shape to Route Keepout" "0 MIL [DEFAULT]" "0 MIL" "0.00 MIL" "DRC ERROR CLASS/BOTTOM" "[Shape] Route Keepout/All ((2523.47 2216.68) (2567.09 2338.3))" "[Bottom Shape] GND ((-679.11 -19.37) (3281.09 4854.01))" list(2567.090000 2316.490000) nil)@@@list("bobo_dong" "2014/01/13 20:49:12" nil "S0DCOA89102" "g1t-p0jac.11")@@@nil | list("[Physical] BOTTOM" "46.Pad/Pad Direct Connect" "VIAS_PINS_ONLY [85OHM(DP_#1/#2/5/200)]" "ALL_ALLOWED" "" "DRC ERROR CLASS/BOTTOM" "[SmdPin] DDI0_TX1_DN_R (<uTiL>cId2112<uTiL>.3) (2739.79 1843.85)" "[SmdPin] DDI0_TX1_DN_R (<uTiL>cId2167<uTiL>.4) (2737.82 1841.88)" list(2737.820000 1841.880000) nil)@@@list("bobo_dong" "2014/01/27 15:52:49" nil "s0dcoa89102" "g1t-p0jac.11")@@@list("vincent_kuo" "2014/02/26 15:24:30" nil "VINCENT_KUO-PC" "g1t-p0jac_byt-t.14") | list("[Physical] BOTTOM" "44.Pad/Pad Direct Connect" "VIAS_PINS_ONLY [85OHM(DP_#1/#2/5/200)]" "ALL_ALLOWED" "" "DRC ERROR CLASS/BOTTOM" "[SmdPin] DDI0_TX1_DP_R (<uTiL>cId2112<uTiL>.1) (2739.79 1818.25)" "[SmdPin] DDI0_TX1_DP_R (<uTiL>cId2167<uTiL>.1) (2737.82 1820.22)" list(2737.820000 1820.220000) nil)@@@list("bobo_dong" "2014/01/27 15:52:47" nil "s0dcoa89102" "g1t-p0jac.11")@@@list("vincent_kuo" "2014/02/26 15:24:28" nil "VINCENT_KUO-PC" "g1t-p0jac_byt-t.14") | list("[Physical] BOTTOM" "12.Pad/Pad Direct Connect" "VIAS_PINS_ONLY [85OHM(DP_#1/#2/5/200)]" "ALL_ALLOWED" "" "DRC ERROR CLASS/BOTTOM" "[SmdPin] USB2_DP (<uTiL>cId3907<uTiL>.2) (2736.12 2264.81)" "[SmdPin] USB2_DP (<uTiL>cId3864<uTiL>.3) (2738.09 2266.78)" list(2738.090000 2266.780000) nil)@@@list("bobo_dong" "2014/01/27 15:52:11" nil "s0dcoa89102" "g1t-p0jac.11")@@@list("vincent_kuo" "2014/02/26 15:23:47" nil "VINCENT_KUO-PC" "g1t-p0jac_byt-t.14") | list("[Physical] BOTTOM" "15.Pad/Pad Direct Connect" "VIAS_PINS_ONLY [85OHM(DP_#1/#2/5/200)]" "ALL_ALLOWED" "" "DRC ERROR CLASS/BOTTOM" "[SmdPin] USB2_DN (<uTiL>cId3907<uTiL>.3) (2736.12 2243.15)" "[SmdPin] USB2_DN (<uTiL>cId3864<uTiL>.1) (2738.09 2241.18)" list(2738.090000 2241.180000) nil)@@@list("bobo_dong" "2014/01/27 15:52:13" nil "s0dcoa89102" "g1t-p0jac.11")@@@list("vincent_kuo" "2014/02/26 15:23:51" nil "VINCENT_KUO-PC" "g1t-p0jac_byt-t.14") | list("[Physical] BOTTOM" "38.Pad/Pad Direct Connect" "VIAS_PINS_ONLY [85OHM(DP_#1/#2/5/200)]" "ALL_ALLOWED" "" "DRC ERROR CLASS/BOTTOM" "[SmdPin] DDI0_TX0_DN_R (<uTiL>cId2168<uTiL>.4) (2737.82 1721.88)" "[SmdPin] DDI0_TX0_DN_R (<uTiL>cId2113<uTiL>.3) (2739.79 1723.85)" list(2739.790000 1723.850000) nil)@@@list("bobo_dong" "2014/01/27 15:52:40" nil "s0dcoa89102" "g1t-p0jac.11")@@@list("vincent_kuo" "2014/02/26 15:24:22" nil "VINCENT_KUO-PC" "g1t-p0jac_byt-t.14") | list("[Physical] BOTTOM" "36.Pad/Pad Direct Connect" "VIAS_PINS_ONLY [85OHM(DP_#1/#2/5/200)]" "ALL_ALLOWED" "" "DRC ERROR CLASS/BOTTOM" "[SmdPin] DDI0_TX0_DP_R (<uTiL>cId2168<uTiL>.1) (2737.82 1700.22)" "[SmdPin] DDI0_TX0_DP_R (<uTiL>cId2113<uTiL>.1) (2739.79 1698.25)" list(2739.790000 1698.250000) nil)@@@list("bobo_dong" "2014/01/27 15:52:37" nil "s0dcoa89102" "g1t-p0jac.11")@@@list("vincent_kuo" "2014/02/26 15:24:20" nil "VINCENT_KUO-PC" "g1t-p0jac_byt-t.14") | list("[Physical] BOTTOM" "50.Pad/Pad Direct Connect" "VIAS_PINS_ONLY [85OHM(DP_#1/#2/5/200)]" "ALL_ALLOWED" "" "DRC ERROR CLASS/BOTTOM" "[SmdPin] DDI0_TX2_DN_R (<uTiL>cId2166<uTiL>.4) (2737.82 1597.88)" "[SmdPin] DDI0_TX2_DN_R (<uTiL>cId2111<uTiL>.3) (2739.79 1599.85)" list(2739.790000 1599.850000) nil)@@@list("bobo_dong" "2014/01/27 15:52:52" nil "s0dcoa89102" "g1t-p0jac.11")@@@list("vincent_kuo" "2014/02/26 15:24:34" nil "VINCENT_KUO-PC" "g1t-p0jac_byt-t.14") | list("[Physical] BOTTOM" "48.Pad/Pad Direct Connect" "VIAS_PINS_ONLY [85OHM(DP_#1/#2/5/200)]" "ALL_ALLOWED" "" "DRC ERROR CLASS/BOTTOM" "[SmdPin] DDI0_TX2_DP_R (<uTiL>cId2166<uTiL>.1) (2737.82 1576.22)" "[SmdPin] DDI0_TX2_DP_R (<uTiL>cId2111<uTiL>.1) (2739.79 1574.25)" list(2739.790000 1574.250000) nil)@@@list("bobo_dong" "2014/01/27 15:52:51" nil "s0dcoa89102" "g1t-p0jac.11")@@@list("vincent_kuo" "2014/02/26 15:24:32" nil "VINCENT_KUO-PC" "g1t-p0jac_byt-t.14") | list("[Physical] BOTTOM" "40.Pad/Pad Direct Connect" "VIAS_PINS_ONLY [85OHM(DP_#1/#2/5/200)]" "ALL_ALLOWED" "" "DRC ERROR CLASS/BOTTOM" "[SmdPin] DDI0_TX3_DN_R (<uTiL>cId2165<uTiL>.4) (2737.82 1475.88)" "[SmdPin] DDI0_TX3_DN_R (<uTiL>cId2110<uTiL>.3) (2739.79 1477.85)" list(2739.790000 1477.850000) nil)@@@list("bobo_dong" "2014/01/27 15:52:42" nil "s0dcoa89102" "g1t-p0jac.11")@@@list("vincent_kuo" "2014/02/26 15:24:24" nil "VINCENT_KUO-PC" "g1t-p0jac_byt-t.14") | list("[Physical] BOTTOM" "42.Pad/Pad Direct Connect" "VIAS_PINS_ONLY [85OHM(DP_#1/#2/5/200)]" "ALL_ALLOWED" "" "DRC ERROR CLASS/BOTTOM" "[SmdPin] DDI0_TX3_DP_R (<uTiL>cId2165<uTiL>.1) (2737.82 1454.22)" "[SmdPin] DDI0_TX3_DP_R (<uTiL>cId2110<uTiL>.1) (2739.79 1452.25)" list(2739.790000 1452.250000) nil)@@@list("bobo_dong" "2014/01/27 15:52:45" nil "s0dcoa89102" "g1t-p0jac.11")@@@list("vincent_kuo" "2014/02/26 15:24:26" nil "VINCENT_KUO-PC" "g1t-p0jac_byt-t.14") | list("[Physical] BOTTOM" "13.Pad/Pad Direct Connect" "VIAS_PINS_ONLY [85OHM(DP_#1/#2/5/200)]" "ALL_ALLOWED" "" "DRC ERROR CLASS/BOTTOM" "[SmdPin] 85_USB2_CPU_P1_DP_C (<uTiL>cId3907<uTiL>.1) (2785.34 2264.81)" "[SmdPin] 85_USB2_CPU_P1_DP_C (<uTiL>cId3864<uTiL>.4) (2783.37 2266.78)" list(2783.370000 2266.780000) nil)@@@list("bobo_dong" "2014/01/27 15:52:11" nil "s0dcoa89102" "g1t-p0jac.11")@@@list("vincent_kuo" "2014/02/26 15:23:48" nil "VINCENT_KUO-PC" "g1t-p0jac_byt-t.14") | list("[Physical] BOTTOM" "14.Pad/Pad Direct Connect" "VIAS_PINS_ONLY [85OHM(DP_#1/#2/5/200)]" "ALL_ALLOWED" "" "DRC ERROR CLASS/BOTTOM" "[SmdPin] 85_USB2_CPU_P1_DN_C (<uTiL>cId3907<uTiL>.4) (2785.34 2243.15)" "[SmdPin] 85_USB2_CPU_P1_DN_C (<uTiL>cId3864<uTiL>.2) (2783.37 2241.18)" list(2783.370000 2241.180000) nil)@@@list("bobo_dong" "2014/01/27 15:52:12" nil "s0dcoa89102" "g1t-p0jac.11")@@@list("vincent_kuo" "2014/02/26 15:23:49" nil "VINCENT_KUO-PC" "g1t-p0jac_byt-t.14") | list("[Physical] BOTTOM" "39.Pad/Pad Direct Connect" "VIAS_PINS_ONLY [85OHM(DP_#1/#2/5/200)]" "ALL_ALLOWED" "" "DRC ERROR CLASS/BOTTOM" "[SmdPin] HDMI_DATA2_DN_CON (<uTiL>cId2168<uTiL>.3) (2787.04 1721.88)" "[SmdPin] HDMI_DATA2_DN_CON (<uTiL>cId2113<uTiL>.4) (2785.07 1723.85)" list(2785.070000 1723.850000) nil)@@@list("bobo_dong" "2014/01/27 15:52:39" nil "s0dcoa89102" "g1t-p0jac.11")@@@list("vincent_kuo" "2014/02/26 15:24:23" nil "VINCENT_KUO-PC" "g1t-p0jac_byt-t.14") | list("[Physical] BOTTOM" "37.Pad/Pad Direct Connect" "VIAS_PINS_ONLY [85OHM(DP_#1/#2/5/200)]" "ALL_ALLOWED" "" "DRC ERROR CLASS/BOTTOM" "[SmdPin] HDMI_DATA2_DP_CON (<uTiL>cId2168<uTiL>.2) (2787.04 1700.22)" "[SmdPin] HDMI_DATA2_DP_CON (<uTiL>cId2113<uTiL>.2) (2785.07 1698.25)" list(2785.070000 1698.250000) nil)@@@list("bobo_dong" "2014/01/27 15:52:41" nil "s0dcoa89102" "g1t-p0jac.11")@@@list("vincent_kuo" "2014/02/26 15:24:21" nil "VINCENT_KUO-PC" "g1t-p0jac_byt-t.14") | list("[Physical] BOTTOM" "51.Pad/Pad Direct Connect" "VIAS_PINS_ONLY [85OHM(DP_#1/#2/5/200)]" "ALL_ALLOWED" "" "DRC ERROR CLASS/BOTTOM" "[SmdPin] HDMI_DATA0_DN_CON (<uTiL>cId2166<uTiL>.3) (2787.04 1597.88)" "[SmdPin] HDMI_DATA0_DN_CON (<uTiL>cId2111<uTiL>.4) (2785.07 1599.85)" list(2785.070000 1599.850000) nil)@@@list("bobo_dong" "2014/01/27 15:52:51" nil "s0dcoa89102" "g1t-p0jac.11")@@@list("vincent_kuo" "2014/02/26 15:24:36" nil "VINCENT_KUO-PC" "g1t-p0jac_byt-t.14") | list("[Physical] BOTTOM" "49.Pad/Pad Direct Connect" "VIAS_PINS_ONLY [85OHM(DP_#1/#2/5/200)]" "ALL_ALLOWED" "" "DRC ERROR CLASS/BOTTOM" "[SmdPin] HDMI_DATA0_DP_CON (<uTiL>cId2166<uTiL>.2) (2787.04 1576.22)" "[SmdPin] HDMI_DATA0_DP_CON (<uTiL>cId2111<uTiL>.2) (2785.07 1574.25)" list(2785.070000 1574.250000) nil)@@@list("bobo_dong" "2014/01/27 15:52:53" nil "s0dcoa89102" "g1t-p0jac.11")@@@list("vincent_kuo" "2014/02/26 15:24:33" nil "VINCENT_KUO-PC" "g1t-p0jac_byt-t.14") | list("[Physical] BOTTOM" "41.Pad/Pad Direct Connect" "VIAS_PINS_ONLY [85OHM(DP_#1/#2/5/200)]" "ALL_ALLOWED" "" "DRC ERROR CLASS/BOTTOM" "[SmdPin] HDMI_CLK_DN_CON (<uTiL>cId2165<uTiL>.3) (2787.04 1475.88)" "[SmdPin] HDMI_CLK_DN_CON (<uTiL>cId2110<uTiL>.4) (2785.07 1477.85)" list(2785.070000 1477.850000) nil)@@@list("bobo_dong" "2014/01/27 15:52:44" nil "s0dcoa89102" "g1t-p0jac.11")@@@list("vincent_kuo" "2014/02/26 15:24:25" nil "VINCENT_KUO-PC" "g1t-p0jac_byt-t.14") | list("[Physical] BOTTOM" "43.Pad/Pad Direct Connect" "VIAS_PINS_ONLY [85OHM(DP_#1/#2/5/200)]" "ALL_ALLOWED" "" "DRC ERROR CLASS/BOTTOM" "[SmdPin] HDMI_CLK_DP_CON (<uTiL>cId2165<uTiL>.2) (2787.04 1454.22)" "[SmdPin] HDMI_CLK_DP_CON (<uTiL>cId2110<uTiL>.2) (2785.07 1452.25)" list(2785.070000 1452.250000) nil)@@@list("bobo_dong" "2014/01/27 15:52:46" nil "s0dcoa89102" "g1t-p0jac.11")@@@list("vincent_kuo" "2014/02/26 15:24:27" nil "VINCENT_KUO-PC" "g1t-p0jac_byt-t.14") | list("[Physical] BOTTOM" "47.Pad/Pad Direct Connect" "VIAS_PINS_ONLY [85OHM(DP_#1/#2/5/200)]" "ALL_ALLOWED" "" "DRC ERROR CLASS/BOTTOM" "[SmdPin] HDMI_DATA1_DN_CON (<uTiL>cId2112<uTiL>.4) (2785.07 1843.85)" "[SmdPin] HDMI_DATA1_DN_CON (<uTiL>cId2167<uTiL>.3) (2787.04 1841.88)" list(2787.040000 1841.880000) nil)@@@list("bobo_dong" "2014/01/27 15:52:50" nil "s0dcoa89102" "g1t-p0jac.11")@@@list("vincent_kuo" "2014/02/26 15:24:31" nil "VINCENT_KUO-PC" "g1t-p0jac_byt-t.14") | list("[Physical] BOTTOM" "45.Pad/Pad Direct Connect" "VIAS_PINS_ONLY [85OHM(DP_#1/#2/5/200)]" "ALL_ALLOWED" "" "DRC ERROR CLASS/BOTTOM" "[SmdPin] HDMI_DATA1_DP_CON (<uTiL>cId2112<uTiL>.2) (2785.07 1818.25)" "[SmdPin] HDMI_DATA1_DP_CON (<uTiL>cId2167<uTiL>.2) (2787.04 1820.22)" list(2787.040000 1820.220000) nil)@@@list("bobo_dong" "2014/01/27 15:52:48" nil "s0dcoa89102" "g1t-p0jac.11")@@@list("vincent_kuo" "2014/02/26 15:24:29" nil "VINCENT_KUO-PC" "g1t-p0jac_byt-t.14") | list("[Spacing] BOTTOM" "7.Shape to Route Keepin" "0 MIL [DEFAULT]" "0 MIL" "0.00 MIL" "DRC ERROR CLASS/BOTTOM" "[Shape] Route Keepin/All ((-679.11 -19.37) (3281.09 4854.01))" "[Bottom Shape] GND ((-679.11 -19.37) (3281.09 4854.01))" list(2831.400000 1151.120000) nil)@@@list("bobo_dong" "2014/02/25 09:08:26" nil "s0dcoa89102" "g1t-p0jac.11")@@@list("vincent_kuo" "2014/01/14 20:15:02" nil "VINCENT_KUO-PC" "g1t-p0jac_byt-t.12") | list("[Spacing] BOTTOM" "77.Shape to Route Keepout" "0 MIL [DEFAULT]" "0 MIL" "0.00 MIL" "DRC ERROR CLASS/BOTTOM" "[Shape] Route Keepout/All ((3056.9 2031.81) (3317.13 2375.11))" "[Bottom Shape] GND ((-679.11 -19.37) (3281.09 4854.01))" list(3080.340000 2369.890000) nil)@@@list("bobo_dong" "2014/01/13 20:49:10" nil "S0DCOA89102" "g1t-p0jac.11")@@@nil | list("[Spacing] BOTTOM" "5.Shape to Route Keepin" "0 MIL [DEFAULT]" "0 MIL" "0.00 MIL" "DRC ERROR CLASS/BOTTOM" "[Shape] Route Keepin/All ((-679.11 -19.37) (3281.09 4854.01))" "[Bottom Shape] GND ((-679.11 -19.37) (3281.09 4854.01))" list(3104.240000 2379.050000) nil)@@@list("kelly_lv" "2014/01/14 09:49:43" nil "PC-0005358" "5k-castle.105")@@@list("vincent_kuo" "2014/01/13 22:31:12" nil "VINCENT_KUO-PC" "g1t-p0jac_byt-t.11") | list("[Spacing] BOTTOM" "72.Shape to Route Keepin" "0 MIL [DEFAULT]" "0 MIL" "0.00 MIL" "DRC ERROR CLASS/BOTTOM" "[Shape] Route Keepin/All ((-679.11 -19.37) (3281.09 4854.01))" "[Bottom Shape] GND ((2887.7 4005.9) (3163.29 4282.67))" list(3143.290000 4196.060000) nil)@@@list("bobo_dong" "2014/01/13 20:48:36" nil "S0DCOA89102" "g1t-p0jac.11")@@@nil | list("[Spacing] BOTTOM" "8.Shape to Route Keepin" "0 MIL [DEFAULT]" "0 MIL" "0.00 MIL" "DRC ERROR CLASS/BOTTOM" "[Shape] Route Keepin/All ((-679.11 -19.37) (3281.09 4854.01))" "[Bottom Shape] GND ((-679.11 -19.37) (3281.09 4854.01))" list(3170.940000 1359.560000) nil)@@@list("bobo_dong" "2014/01/15 10:39:23" nil "S0DCOA89102" "g1t-p0jac.11")@@@list("doris_chen" "2014/01/16 14:58:58" nil "JULIA_YU-PC1" "g1t-p0jac_byt-t.13-chk") | list("[Spacing] BOTTOM" "9.Shape to Route Keepin" "0 MIL [DEFAULT]" "0 MIL" "0.00 MIL" "DRC ERROR CLASS/BOTTOM" "[Shape] Route Keepin/All ((-679.11 -19.37) (3281.09 4854.01))" "[Bottom Shape] GND ((-679.11 -19.37) (3281.09 4854.01))" list(3193.600000 1980.710000) nil)@@@list("bobo_dong" "2014/02/25 14:28:35" nil "S0DCOA89102" "g1t-p0jac.11")@@@nil | list("[Spacing] BOTTOM" "71.Shape to Route Keepout" "0 MIL [DEFAULT]" "0 MIL" "0.00 MIL" "DRC ERROR CLASS/BOTTOM" "[Shape] Route Keepout/All ((-699.11 -39.37) (3301.09 4874.01))" "[Bottom Shape] GND ((3242.1 3598.39) (3273.6 3637.76))" list(3242.100000 3637.660000) nil)@@@list("bobo_dong" "2014/01/13 20:48:36" nil "S0DCOA89102" "g1t-p0jac.11")@@@nil | list("[Spacing] BOTTOM" "70.Shape to Route Keepin" "0 MIL [DEFAULT]" "0 MIL" "0.00 MIL" "DRC ERROR CLASS/BOTTOM" "[Shape] Route Keepin/All ((-679.11 -19.37) (3281.09 4854.01))" "[Bottom Shape] GND ((3242.1 3598.39) (3273.6 3637.76))" list(3242.100000 3629.560000) nil)@@@list("bobo_dong" "2014/01/13 20:48:35" nil "S0DCOA89102" "g1t-p0jac.11")@@@nil | list("[Spacing] BOTTOM" "4.Shape to Route Keepin" "0 MIL [DEFAULT]" "0 MIL" "0.00 MIL" "DRC ERROR CLASS/BOTTOM" "[Shape] Route Keepin/All ((-679.11 -19.37) (3281.09 4854.01))" "[Bottom Shape] GND ((-679.11 -19.37) (3281.09 4854.01))" list(3273.590000 3819.170000) nil)@@@nil@@@list("vincent_kuo" "2014/01/13 21:52:03" nil "VINCENT_KUO-PC" "g1t-p0jac_byt-t.11") | list("[Spacing] BOTTOM" "69.Shape to Route Keepin" "0 MIL [DEFAULT]" "0 MIL" "0.00 MIL" "DRC ERROR CLASS/BOTTOM" "[Shape] Route Keepin/All ((-679.11 -19.37) (3281.09 4854.01))" "[Bottom Shape] GND ((3242.1 3810.98) (3273.6 3850.35))" list(3273.600000 3819.170000) nil)@@@list("bobo_dong" "2014/01/13 20:48:26" nil "S0DCOA89102" "g1t-p0jac.11")@@@nil | list("[Spacing] BOTTOM" "68.Shape to Route Keepout" "0 MIL [DEFAULT]" "0 MIL" "0.00 MIL" "DRC ERROR CLASS/BOTTOM" "[Shape] Route Keepout/All ((-699.11 -39.37) (3301.09 4874.01))" "[Bottom Shape] GND ((3242.1 3810.98) (3273.6 3850.35))" list(3273.600000 3811.070000) nil)@@@list("bobo_dong" "2014/01/13 20:48:25" nil "S0DCOA89102" "g1t-p0jac.11")@@@nil | list("[Spacing] BOTTOM" "6.Shape to Route Keepout" "0 MIL [DEFAULT]" "0 MIL" "0.00 MIL" "DRC ERROR CLASS/BOTTOM" "[Shape] Route Keepout/Bottom ((-2617.19 1534.18) (-2400.36 1751.02))" "[Bottom Shape] GND ((-2611.73 -1560.75) (2448.51 1842.01))" list(-2611.160000 1606.910000) nil)@@@list("sky_zheng" "2013/09/13 10:57:35" nil "RDD_704_PC" "g1t-oxygen.10")@@@list("andy_lien" "2013/09/13 12:15:35" nil "ANDY_LIEN-PC" "g1t-oxygen.10") | list("[Spacing] BOTTOM" "10.Thru Via to Route Keepin" "0 MIL [DEFAULT]" "1689.77 MIL" "-1689.77 MIL" "DRC ERROR CLASS/BOTTOM" "[Shape] Route Keepin/All ((-2611.73 -1560.75) (2448.51 1842.01))" "[ThruVia] Dummy (VIA20D10A32) (-2910.0 -2405.0)" list(-2599.980000 -733.740000) nil)@@@list("sky_zheng" "2013/09/13 10:57:37" nil "RDD_704_PC" "g1t-oxygen.10")@@@list("andy_lien" "2013/09/13 12:15:40" nil "ANDY_LIEN-PC" "g1t-oxygen.10") | list("[Spacing] BOTTOM" "9.Thru Via to Route Keepin" "0 MIL [DEFAULT]" "1713.38 MIL" "-1713.38 MIL" "DRC ERROR CLASS/BOTTOM" "[Shape] Route Keepin/All ((-2611.73 -1560.75) (2448.51 1842.01))" "[ThruVia] Dummy (VIA20D10A32) (-2910.0 -2429.0)" list(-2599.940000 -733.750000) nil)@@@list("sky_zheng" "2013/09/13 10:57:38" nil "RDD_704_PC" "g1t-oxygen.10")@@@list("andy_lien" "2013/09/13 12:15:39" nil "ANDY_LIEN-PC" "g1t-oxygen.10") | list("[Spacing] BOTTOM" "5.Shape to Route Keepout" "0 MIL [DEFAULT]" "0 MIL" "0.00 MIL" "DRC ERROR CLASS/BOTTOM" "[Shape] Route Keepout/Bottom ((-2636.95 -749.36) (-2419.97 -532.38))" "[Bottom Shape] GND ((-2611.73 -1560.75) (2448.51 1842.01))" list(-2419.970000 -640.370000) nil)@@@list("sky_zheng" "2013/09/13 10:57:33" nil "RDD_704_PC" "g1t-oxygen.10")@@@list("andy_lien" "2013/09/13 12:15:34" nil "ANDY_LIEN-PC" "g1t-oxygen.10") | list("[Spacing] BOTTOM" "2.Shape to Route Keepin" "0 MIL [DEFAULT]" "0 MIL" "0.00 MIL" "DRC ERROR CLASS/BOTTOM" "[Shape] Route Keepin/All ((-2611.73 -1560.75) (2448.51 1842.01))" "[Bottom Shape] GND ((-2199.6 1385.1) (-2005.01 1752.87))" list(-2195.600000 1424.680000) nil)@@@list("sky_zheng" "2013/09/13 10:57:28" nil "RDD_704_PC" "g1t-oxygen.10")@@@list("andy_lien" "2013/09/13 12:15:29" nil "ANDY_LIEN-PC" "g1t-oxygen.10") | list("[Spacing] BOTTOM" "1.Shape to Route Keepout" "0 MIL [DEFAULT]" "0 MIL" "0.00 MIL" "DRC ERROR CLASS/BOTTOM" "[Shape] Route Keepout/Bottom ((-2660.58 784.69) (-2070.03 1099.65))" "[Bottom Shape] GND ((-2084.41 1044.61) (-2006.49 1161.9))" list(-2070.030000 1044.610000) nil)@@@list("lei_pang" "2013/05/31 15:44:55" nil "TERESA_YU-PC" "15t_ns_mb.100")@@@list("amy_shiu" "2013/05/31 15:07:42" nil "AMY_SHIU-PC2" "15t_ns_mb.100") | list("[Spacing] BOTTOM" "2.Shape to Route Keepin" "0 MIL [DEFAULT]" "0 MIL" "0.00 MIL" "DRC ERROR CLASS/BOTTOM" "[Shape] Route Keepin/All ((-3101.45 -1388.5) (1528.97 1238.07))" "[Bottom Shape] GND ((-2084.41 1044.61) (-2006.49 1161.9))" list(-2068.040000 1153.550000) nil)@@@list("lei_pang" "2013/05/31 15:44:56" nil "TERESA_YU-PC" "15t_ns_mb.100")@@@list("amy_shiu" "2013/05/31 15:07:44" nil "AMY_SHIU-PC2" "15t_ns_mb.100") | list("[Spacing] BOTTOM" "4.Shape to Route Keepout" "0 MIL [DEFAULT]" "0 MIL" "0.00 MIL" "DRC ERROR CLASS/BOTTOM" "[Shape] Route Keepout/All ((-2067.32 694.21) (-1647.5 1044.6))" "[Bottom Shape] GND ((-2084.41 1044.61) (-2006.49 1161.9))" list(-2062.000000 1044.600000) nil)@@@nil@@@list("amy_shiu" "2013/05/31 15:07:44" nil "AMY_SHIU-PC2" "15t_ns_mb.100") | list("[Spacing] BOTTOM" "8.Line to Route Keepin" "0 MIL [DEFAULT]" "0 MIL" "0.00 MIL" "DRC ERROR CLASS/BOTTOM" "[Shape] Route Keepin/All ((-2611.73 -1560.75) (2448.51 1842.01))" "[Line] PLUGDET_CONN_FB ((-1912.97 1479.03) (-1862.9 1491.23))" list(-1863.500000 1485.130000) nil)@@@list("sky_zheng" "2013/09/13 10:57:36" nil "RDD_704_PC" "g1t-oxygen.10")@@@list("andy_lien" "2013/09/13 12:15:37" nil "ANDY_LIEN-PC" "g1t-oxygen.10") | list("[Spacing] BOTTOM" "1.Shape to Route Keepout" "0 MIL [DEFAULT]" "0 MIL" "0.00 MIL" "DRC ERROR CLASS/BOTTOM" "[Shape] Route Keepout/All ((-1971.55 895.0) (-1436.69 1182.41))" "[Bottom Shape] +V5P0S_AUDIO_D ((-1957.96 838.64) (-1735.83 913.6))" list(-1785.860000 905.000000) nil)@@@list("sky_zheng" "2013/09/13 10:57:27" nil "RDD_704_PC" "g1t-oxygen.10")@@@list("andy_lien" "2013/09/13 12:15:28" nil "ANDY_LIEN-PC" "g1t-oxygen.10") | list("[Spacing] BOTTOM" "3.Shape to Route Keepin" "0 MIL [DEFAULT]" "0 MIL" "0.00 MIL" "DRC ERROR CLASS/BOTTOM" "[Shape] Route Keepin/All ((-3101.45 -1388.5) (1528.97 1238.07))" "[Bottom Shape] GND ((-3101.25 -1388.49) (1528.75 1237.87))" list(-1652.400000 1153.550000) nil)@@@list("lei_pang" "2013/05/31 15:44:57" nil "TERESA_YU-PC" "15t_ns_mb.100")@@@list("amy_shiu" "2013/05/31 15:07:40" nil "AMY_SHIU-PC2" "15t_ns_mb.100") | list("[Spacing] BOTTOM" "4.Shape to Route Keepin" "0 MIL [DEFAULT]" "0 MIL" "0.00 MIL" "DRC ERROR CLASS/BOTTOM" "[Shape] Route Keepin/All ((-2611.73 -1560.75) (2448.51 1842.01))" "[Bottom Shape] GND ((-2611.73 -1560.75) (2448.51 1842.01))" list(-13.300000 -778.660000) nil)@@@list("sky_zheng" "2013/09/13 10:57:32" nil "RDD_704_PC" "g1t-oxygen.10")@@@list("andy_lien" "2013/09/13 12:15:33" nil "ANDY_LIEN-PC" "g1t-oxygen.10") | list("[Spacing-SameNet] BOTTOM" "21.Line to Line Same Net" "2.36 MIL [[A]2.36]" "0 MIL" "2.36 MIL" "DRC ERROR CLASS/BOTTOM" "[Line] GND ((23.84 604.74) (38.24 619.14))" "[Line] GND ((30.24 615.68) (40.24 643.86))" list(35.240000 616.140000) nil)@@@list("lei_pang" "2013/05/31 11:02:48" nil "TERESA_YU-PC" "15t_ns_mb.100")@@@nil | list("[Spacing] BOTTOM" "2.Drill Hole to Pin" "8 MIL [DEFAULT]" "4.64 MIL" "3.36 MIL" "DRC ERROR CLASS/BOTTOM" "[ThruPin] Dummy (<uTiL>cId953<uTiL>.7) (882.73 1070.91)" "[SmdPin] GND (<uTiL>cId1946<uTiL>.1) (743.74 1035.06)" list(877.390000 1056.890000) nil)@@@list("lei_pang" "2013/05/31 11:01:52" nil "TERESA_YU-PC" "15t_ns_mb.100")@@@list("amy_shiu" "2013/05/31 11:48:00" nil "amy_shiu-pc2" "15t_ns_mb.100") | list("[Spacing] BOTTOM" "3.Shape to Route Keepout" "0 MIL [DEFAULT]" "0 MIL" "0.00 MIL" "DRC ERROR CLASS/BOTTOM" "[Shape] Route Keepout/Bottom ((2182.03 -946.14) (2398.86 -729.3))" "[Bottom Shape] GND ((-2611.73 -1560.75) (2448.51 1842.01))" list(2182.030000 -836.220000) nil)@@@list("sky_zheng" "2013/09/13 10:57:31" nil "RDD_704_PC" "g1t-oxygen.10")@@@list("andy_lien" "2013/09/13 12:15:31" nil "ANDY_LIEN-PC" "g1t-oxygen.10") | list("[Spacing] BOTTOM" "7.Shape to Route Keepout" "0 MIL [DEFAULT]" "0 MIL" "0.00 MIL" "DRC ERROR CLASS/BOTTOM" "[Shape] Route Keepout/Bottom ((2181.95 1490.8) (2398.93 1707.78))" "[Bottom Shape] GND ((-2611.73 -1560.75) (2448.51 1842.01))" list(2295.250000 1702.670000) nil)@@@list("sky_zheng" "2013/09/13 10:57:34" nil "RDD_704_PC" "g1t-oxygen.10")@@@list("andy_lien" "2013/09/13 12:15:36" nil "ANDY_LIEN-PC" "g1t-oxygen.10")
